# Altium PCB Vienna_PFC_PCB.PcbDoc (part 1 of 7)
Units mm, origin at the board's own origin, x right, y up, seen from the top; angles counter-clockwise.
Board outline 447.04 x 302.51 mm, 6 copper layers (Top Layer, Signal Layer 1, Signal Layer 2, Signal Layer 3, Signal Layer 4, Bottom Layer), stack 1.231 mm thick; 630 components, 255 nets, 1656 pads, 941 vias.
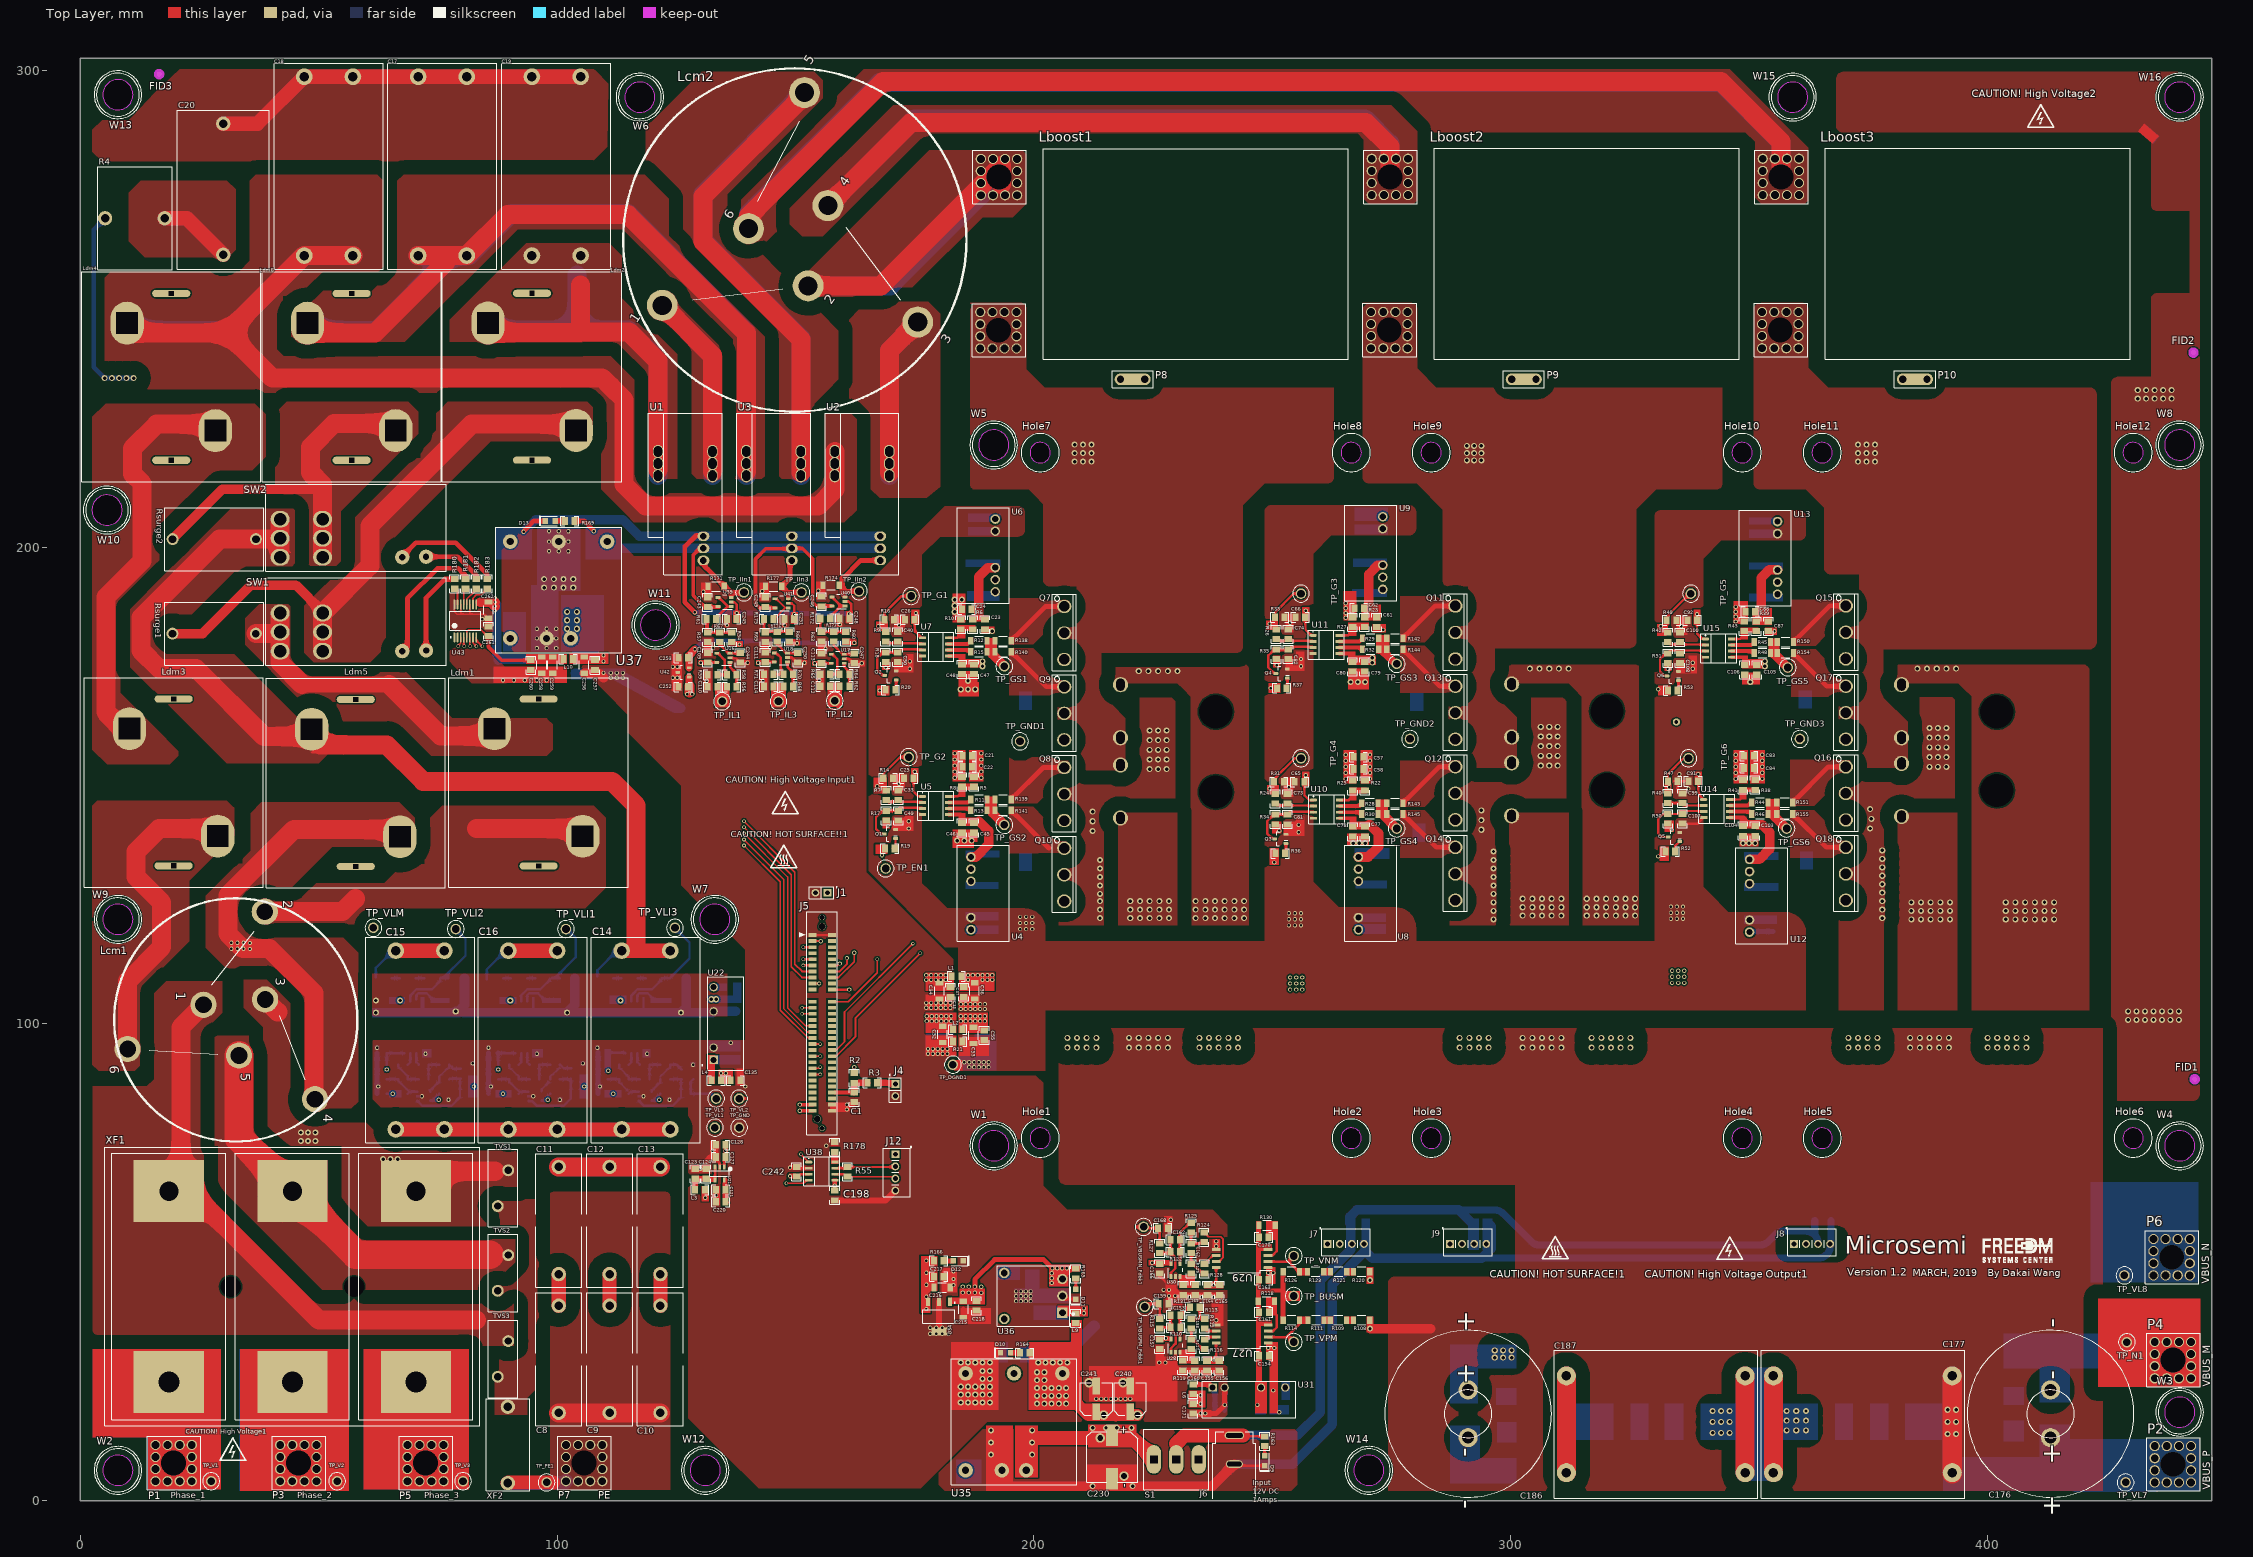
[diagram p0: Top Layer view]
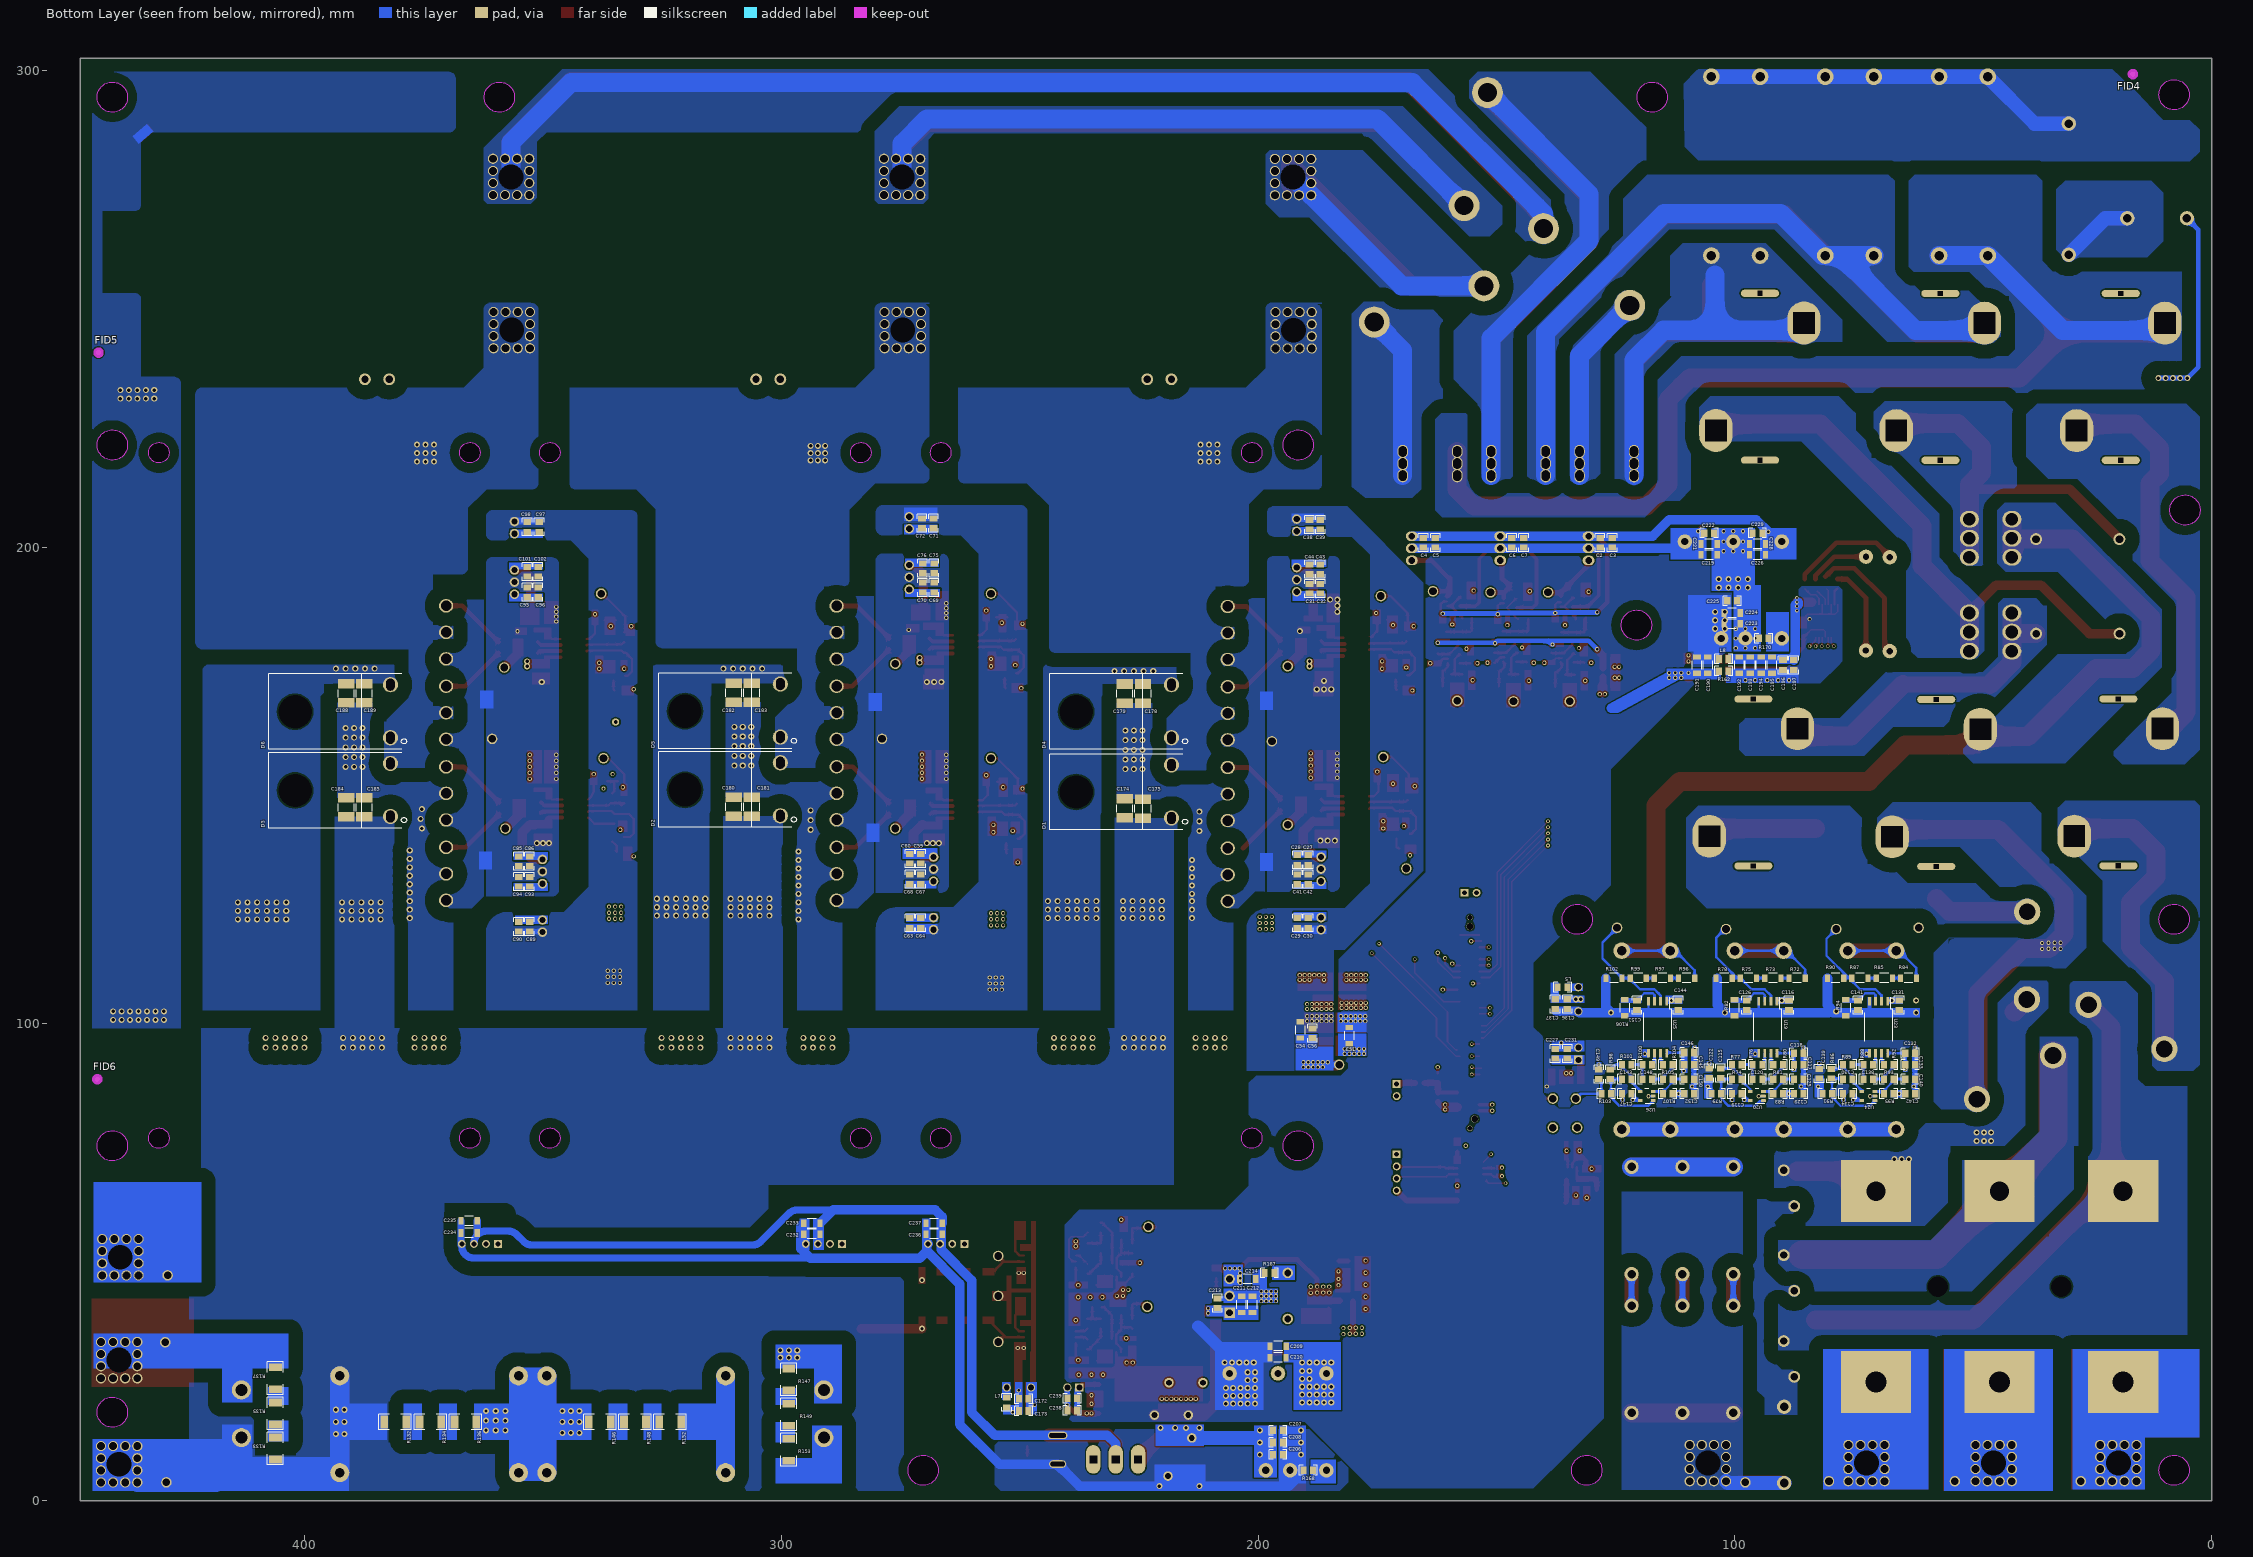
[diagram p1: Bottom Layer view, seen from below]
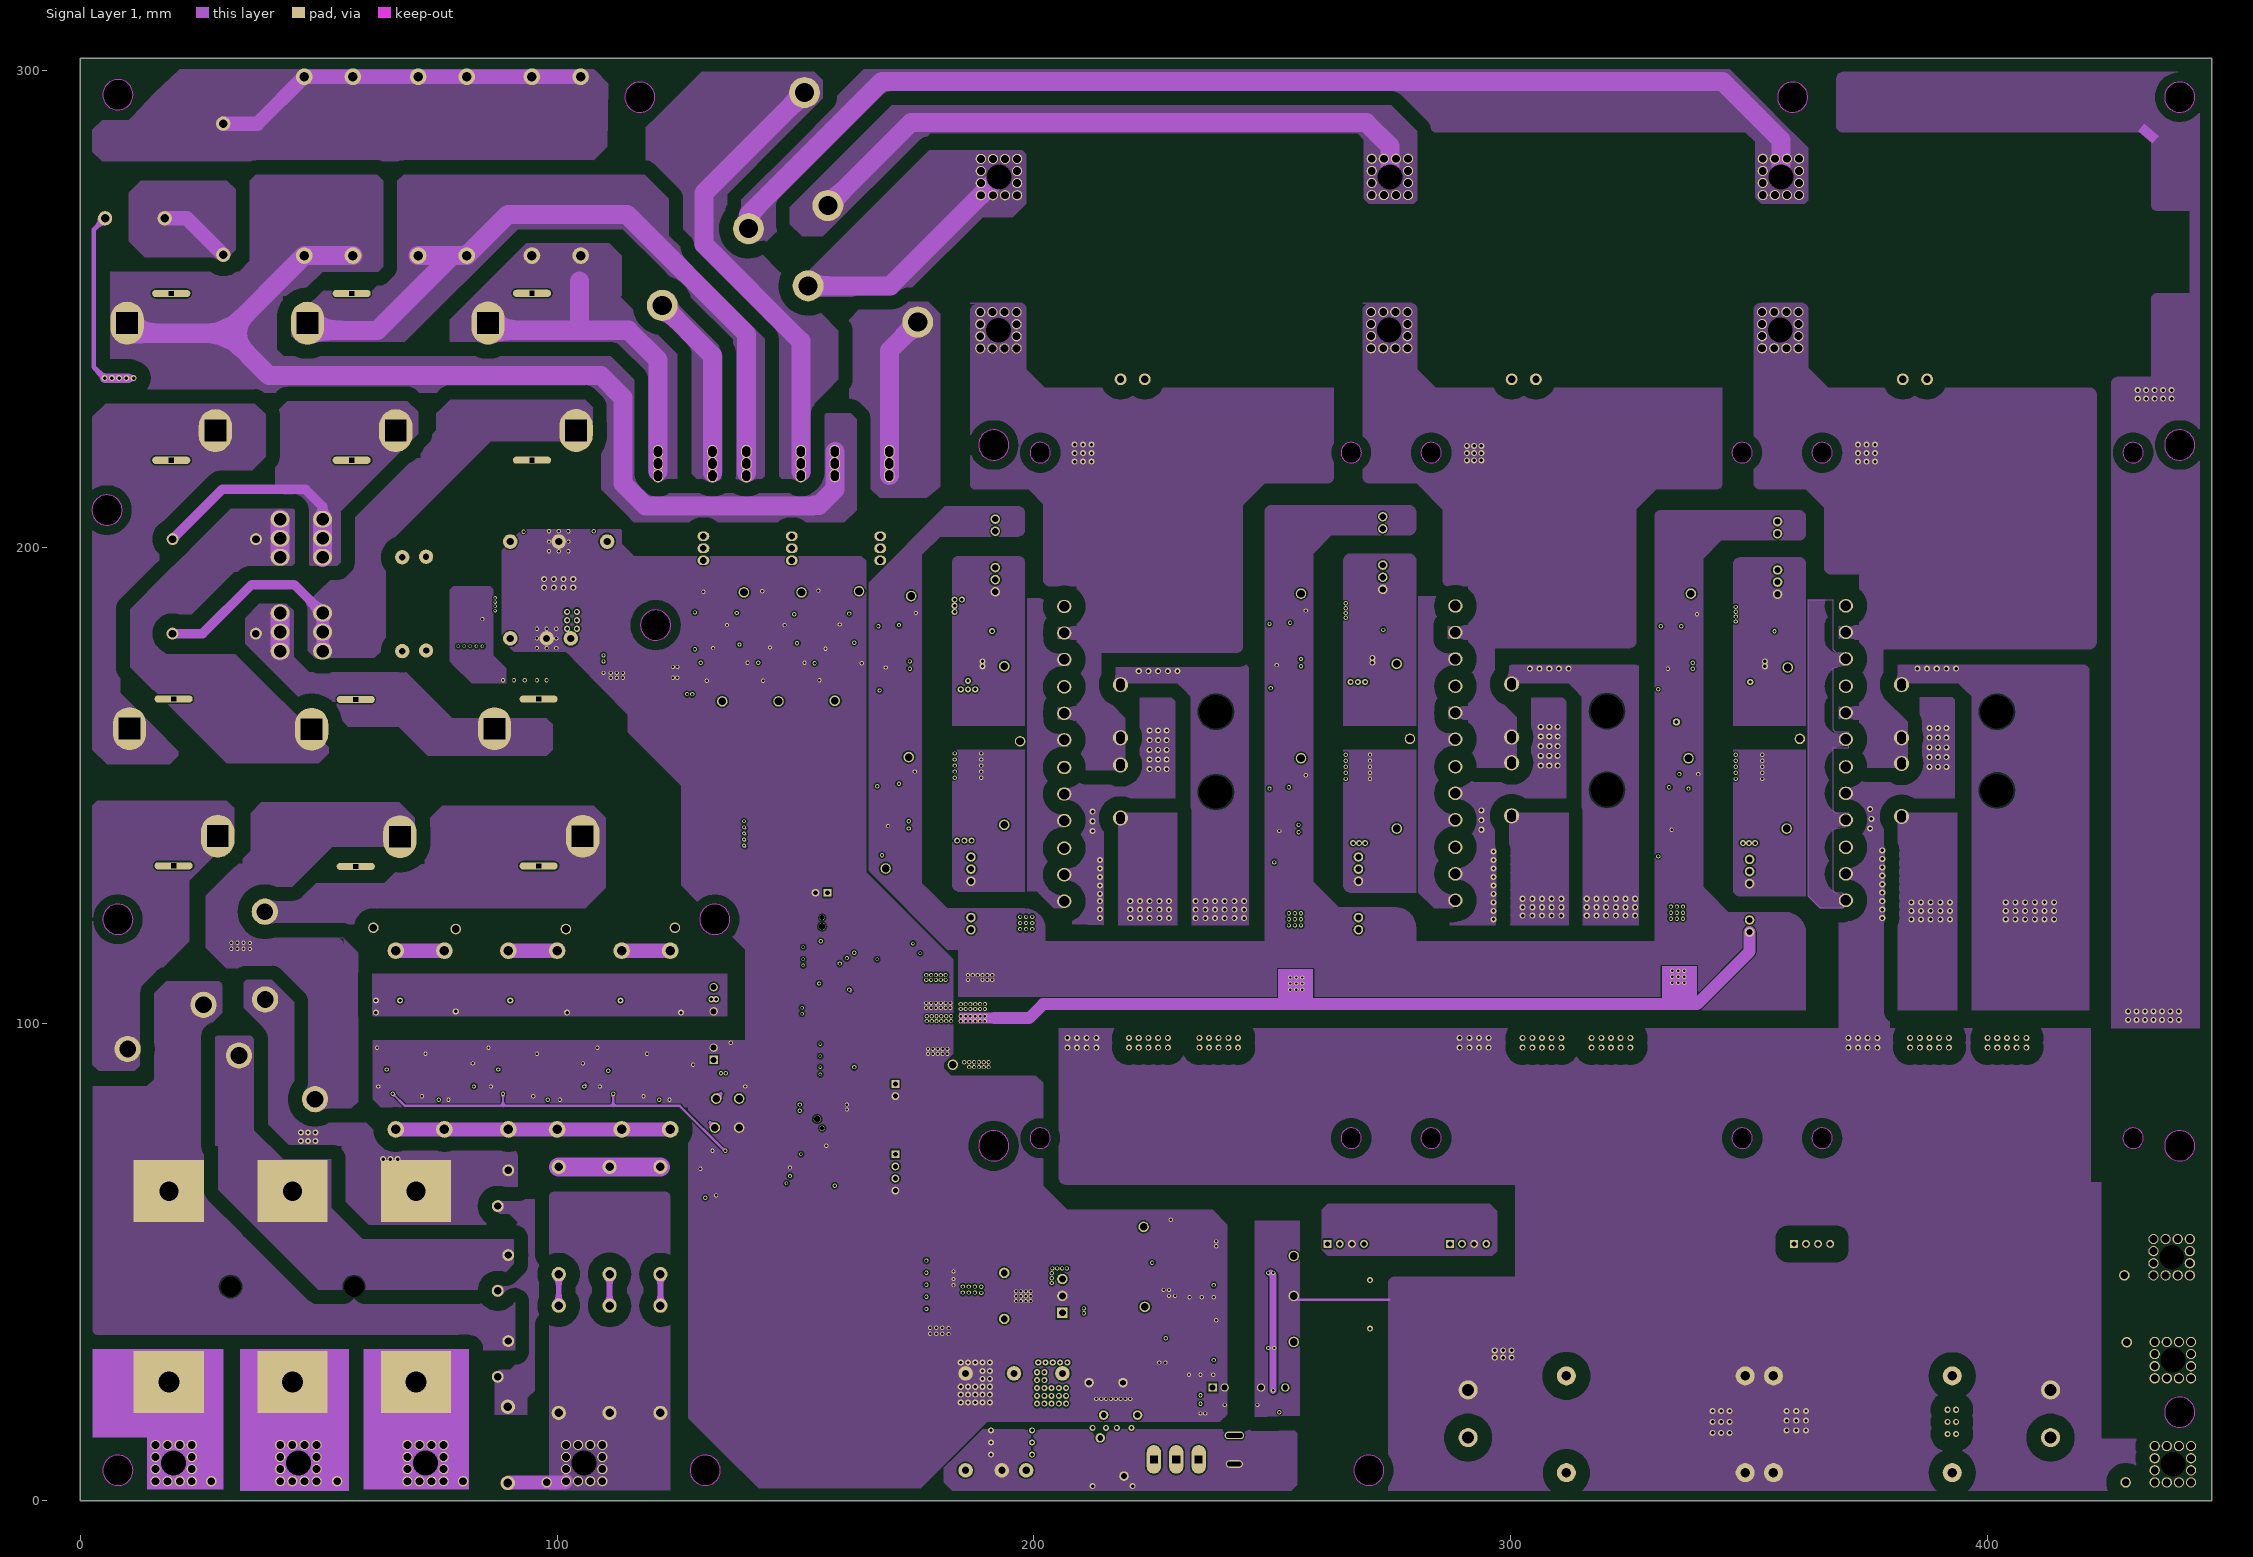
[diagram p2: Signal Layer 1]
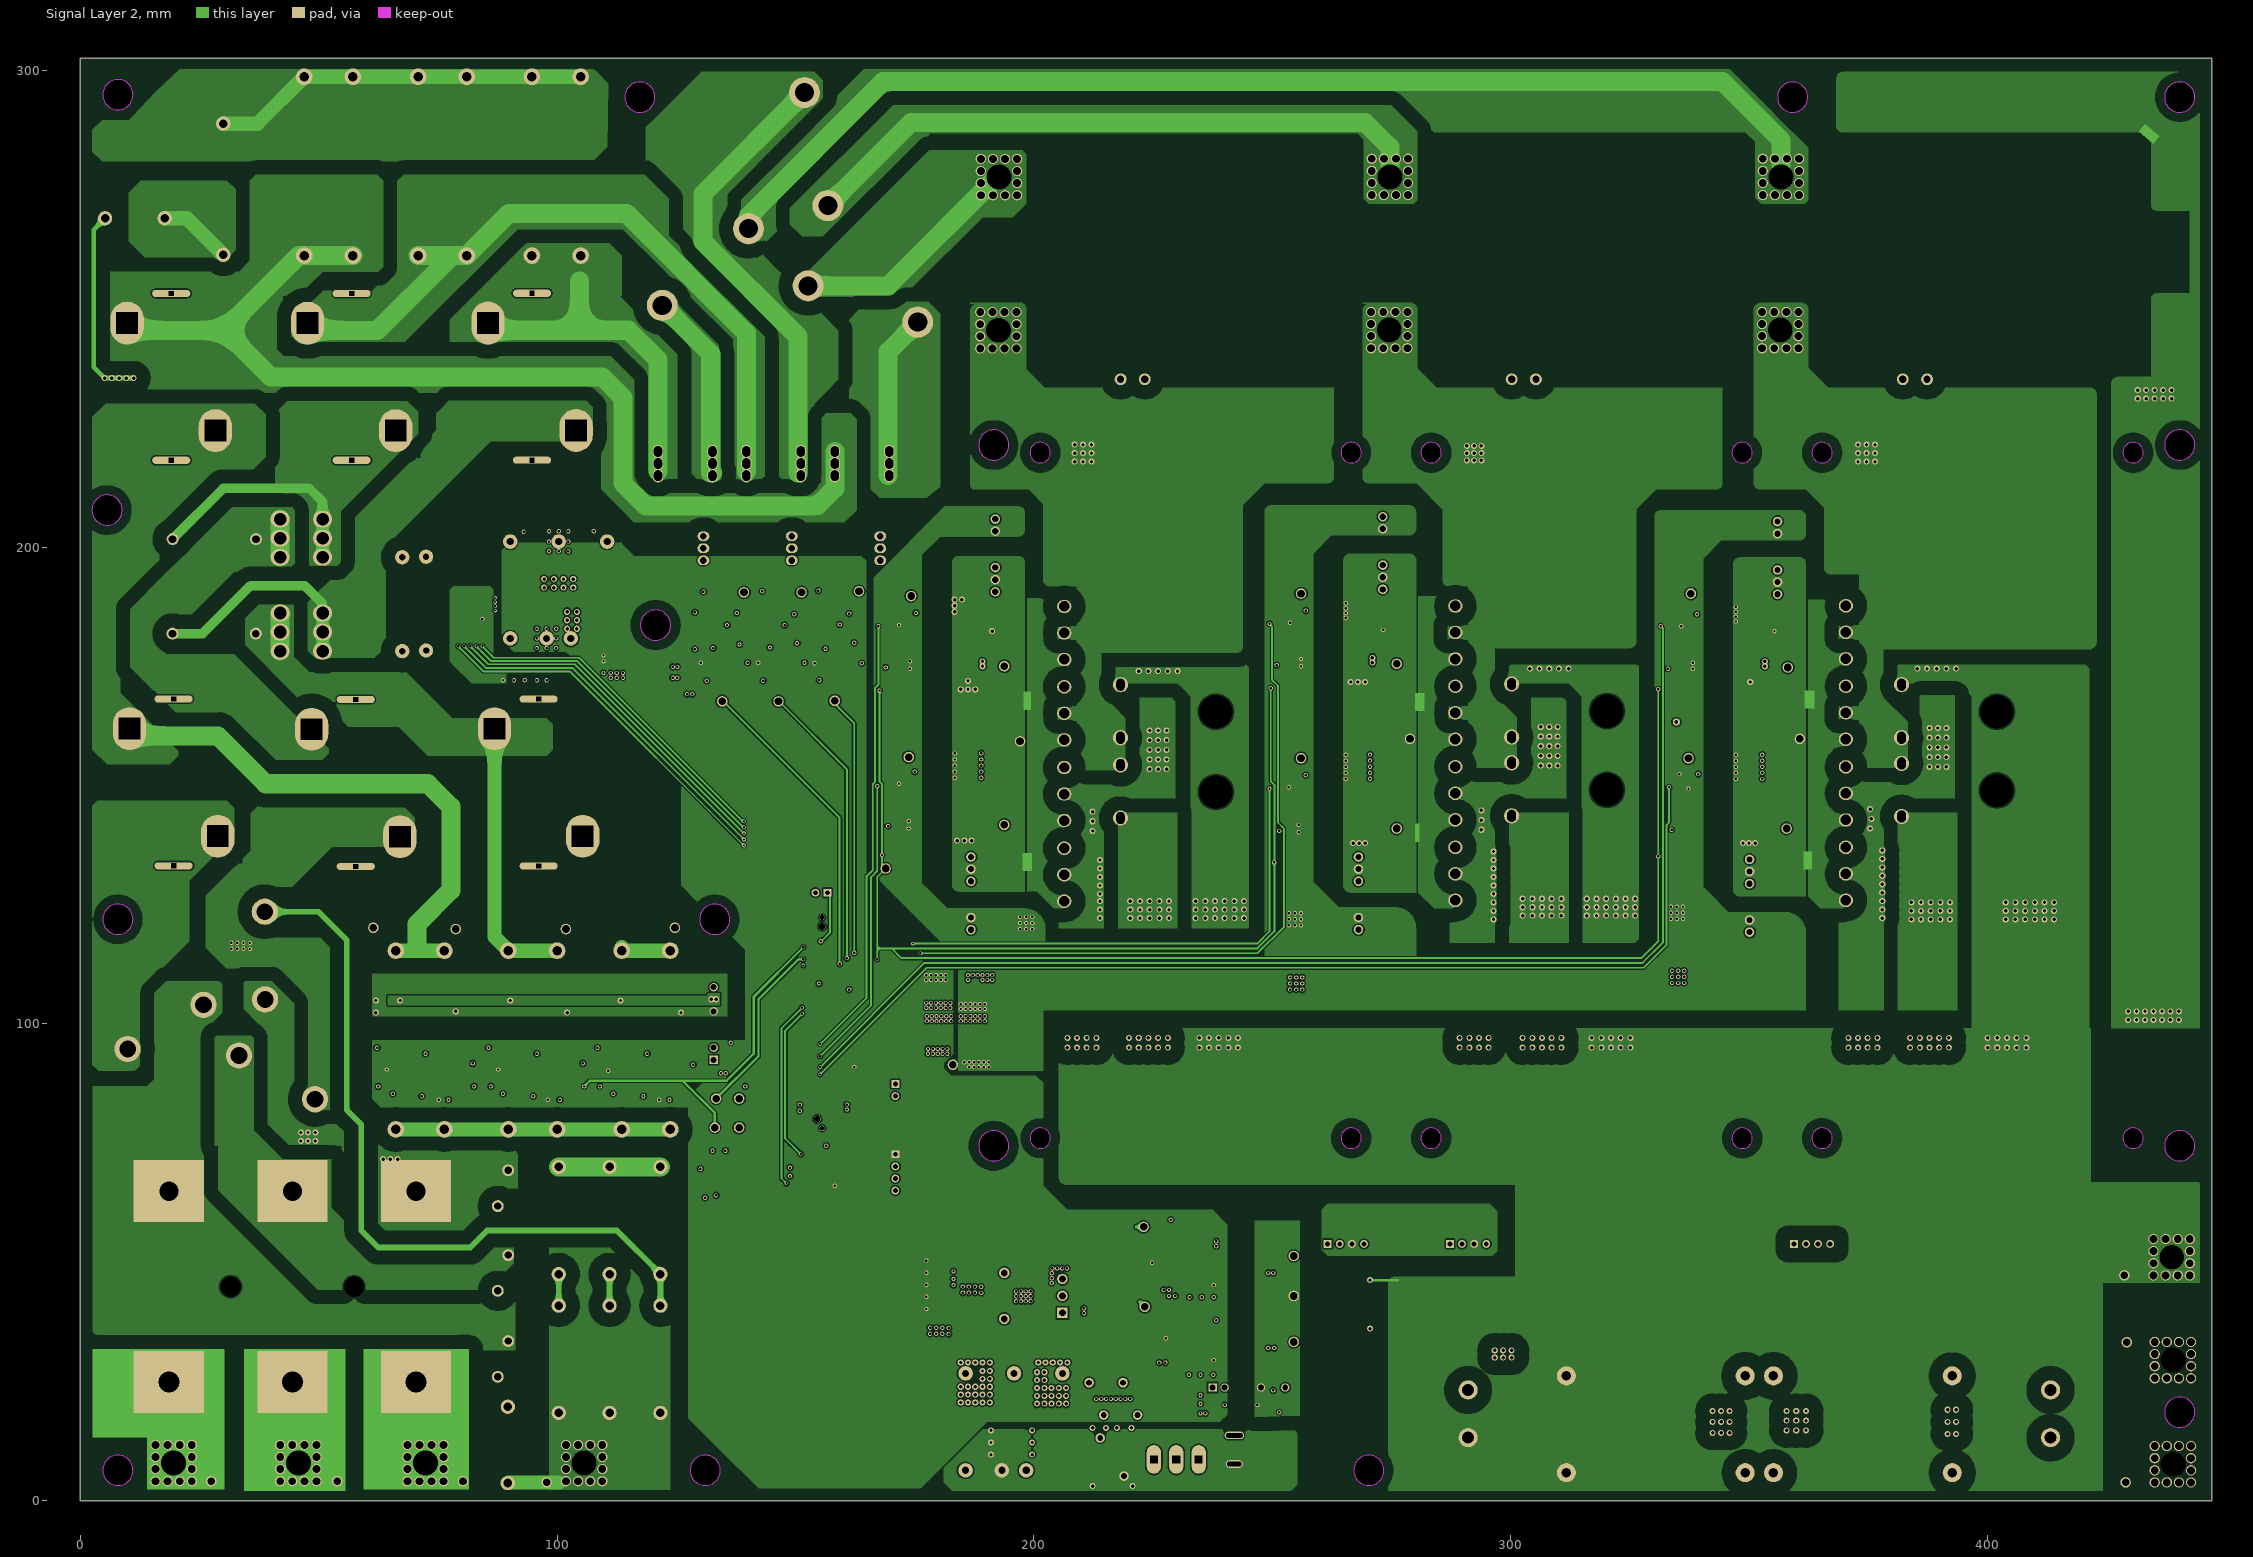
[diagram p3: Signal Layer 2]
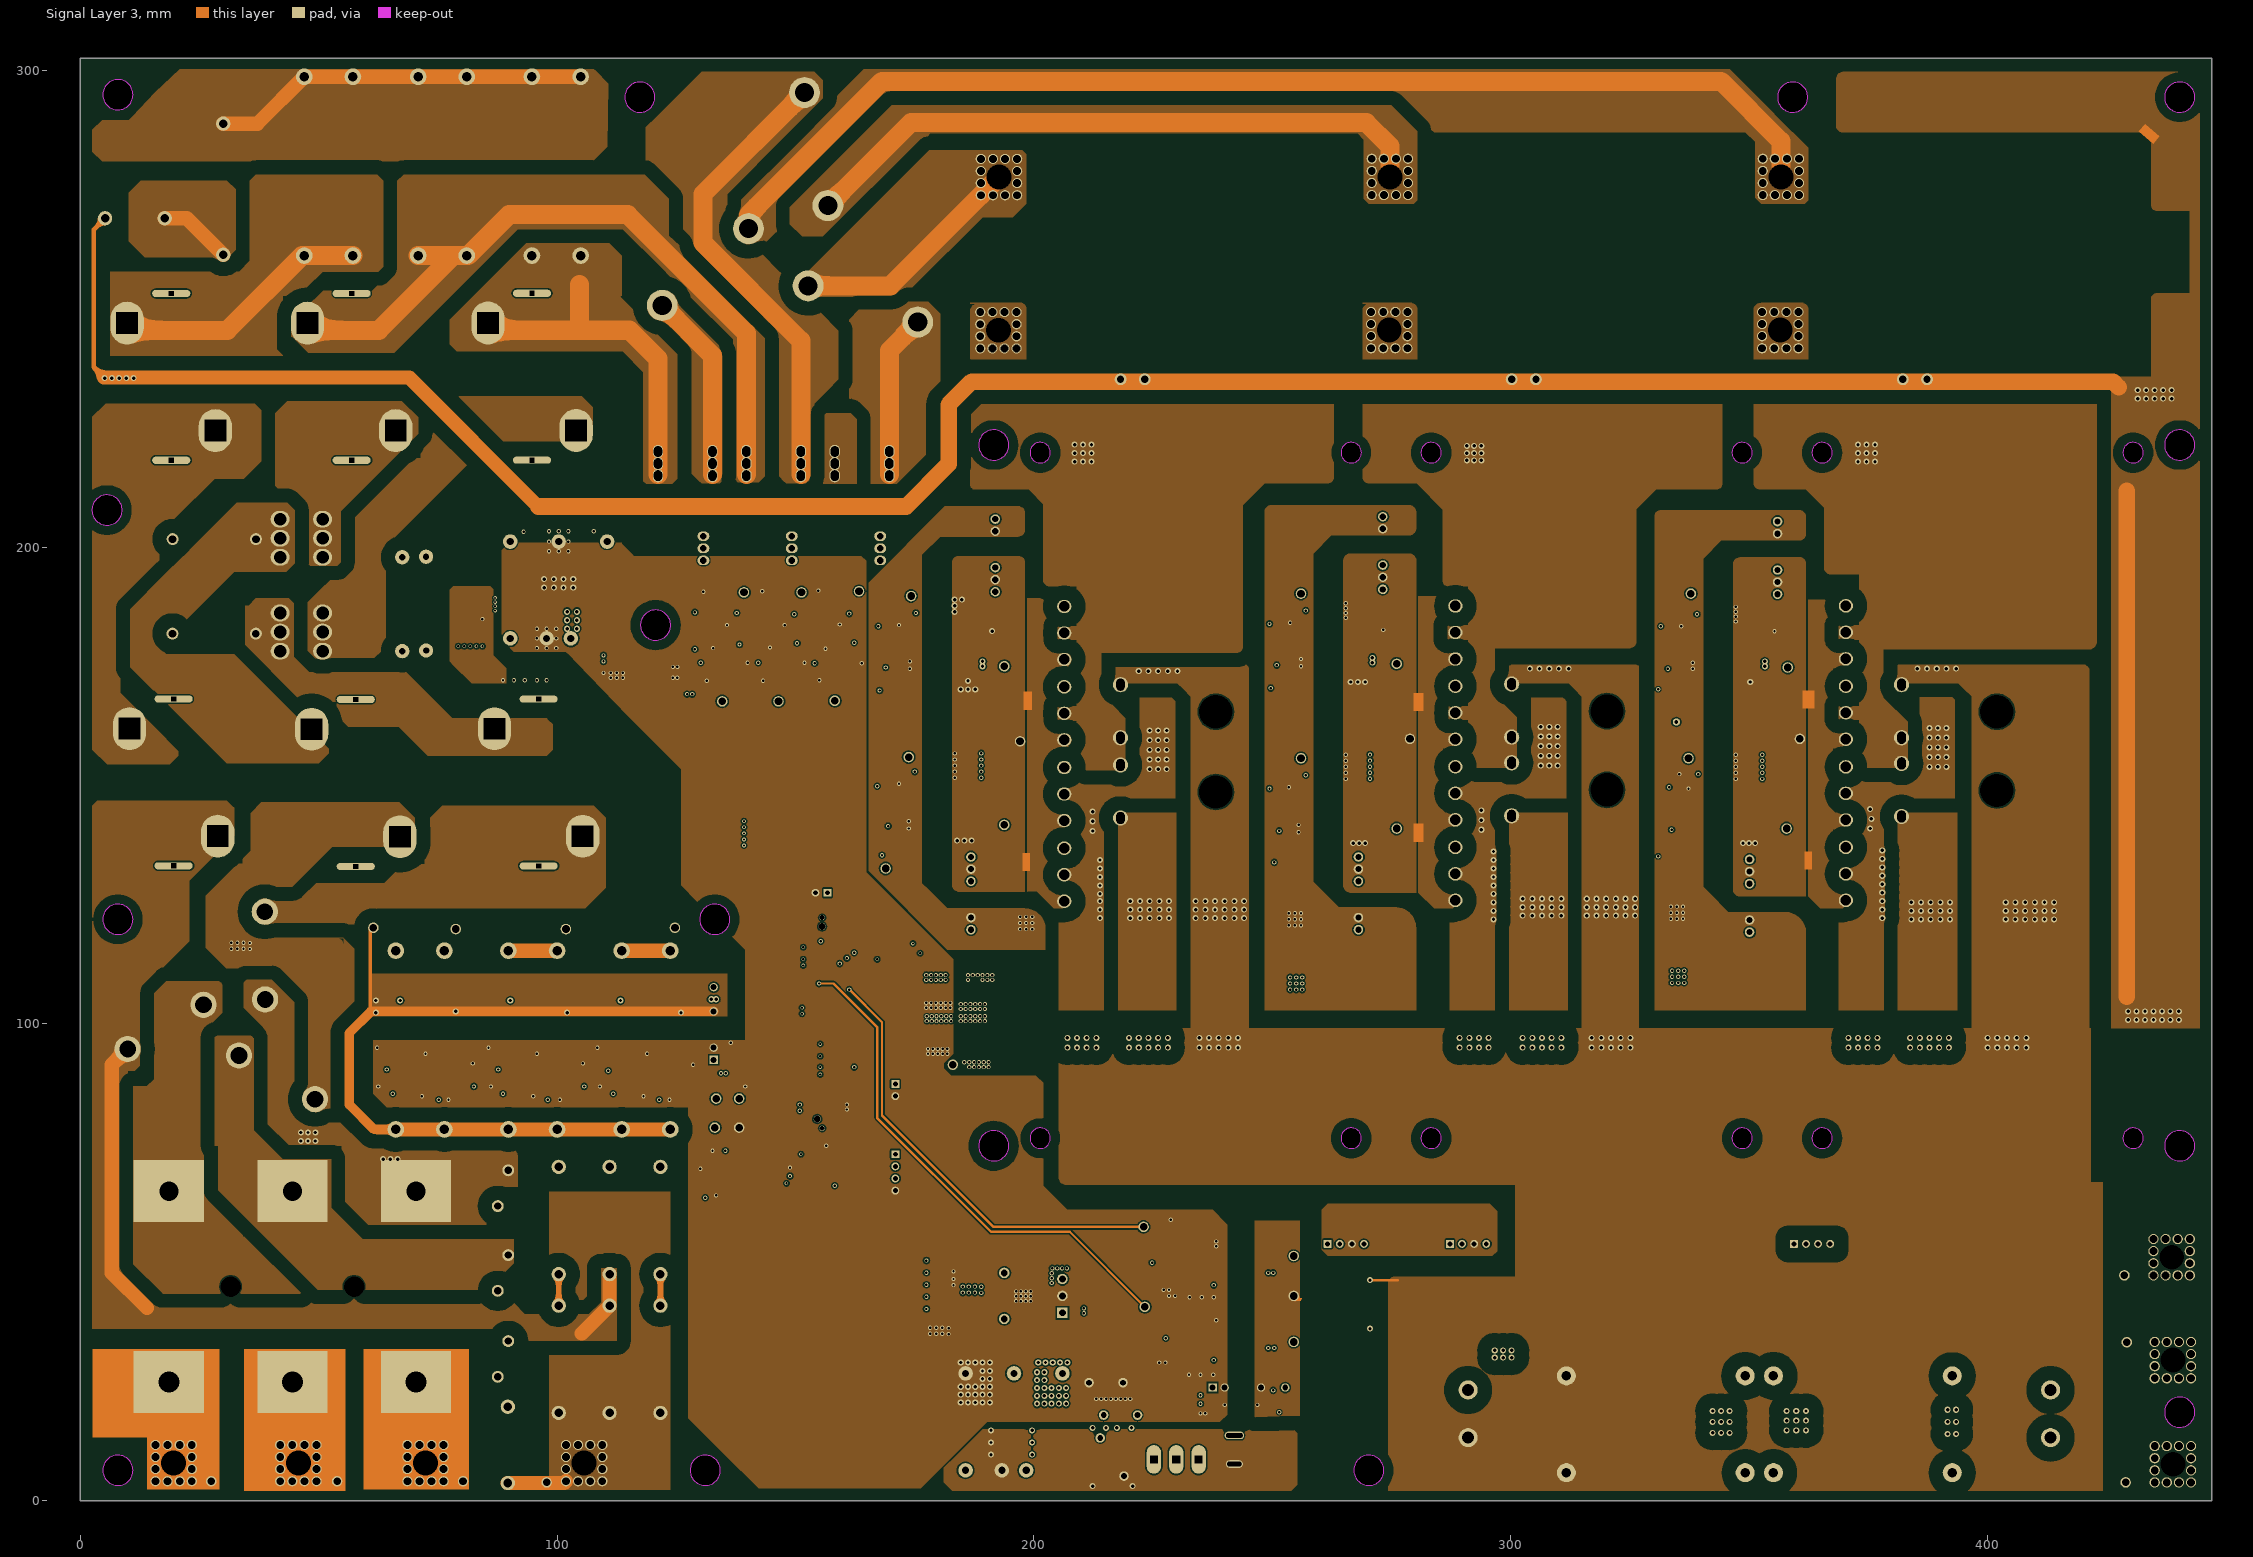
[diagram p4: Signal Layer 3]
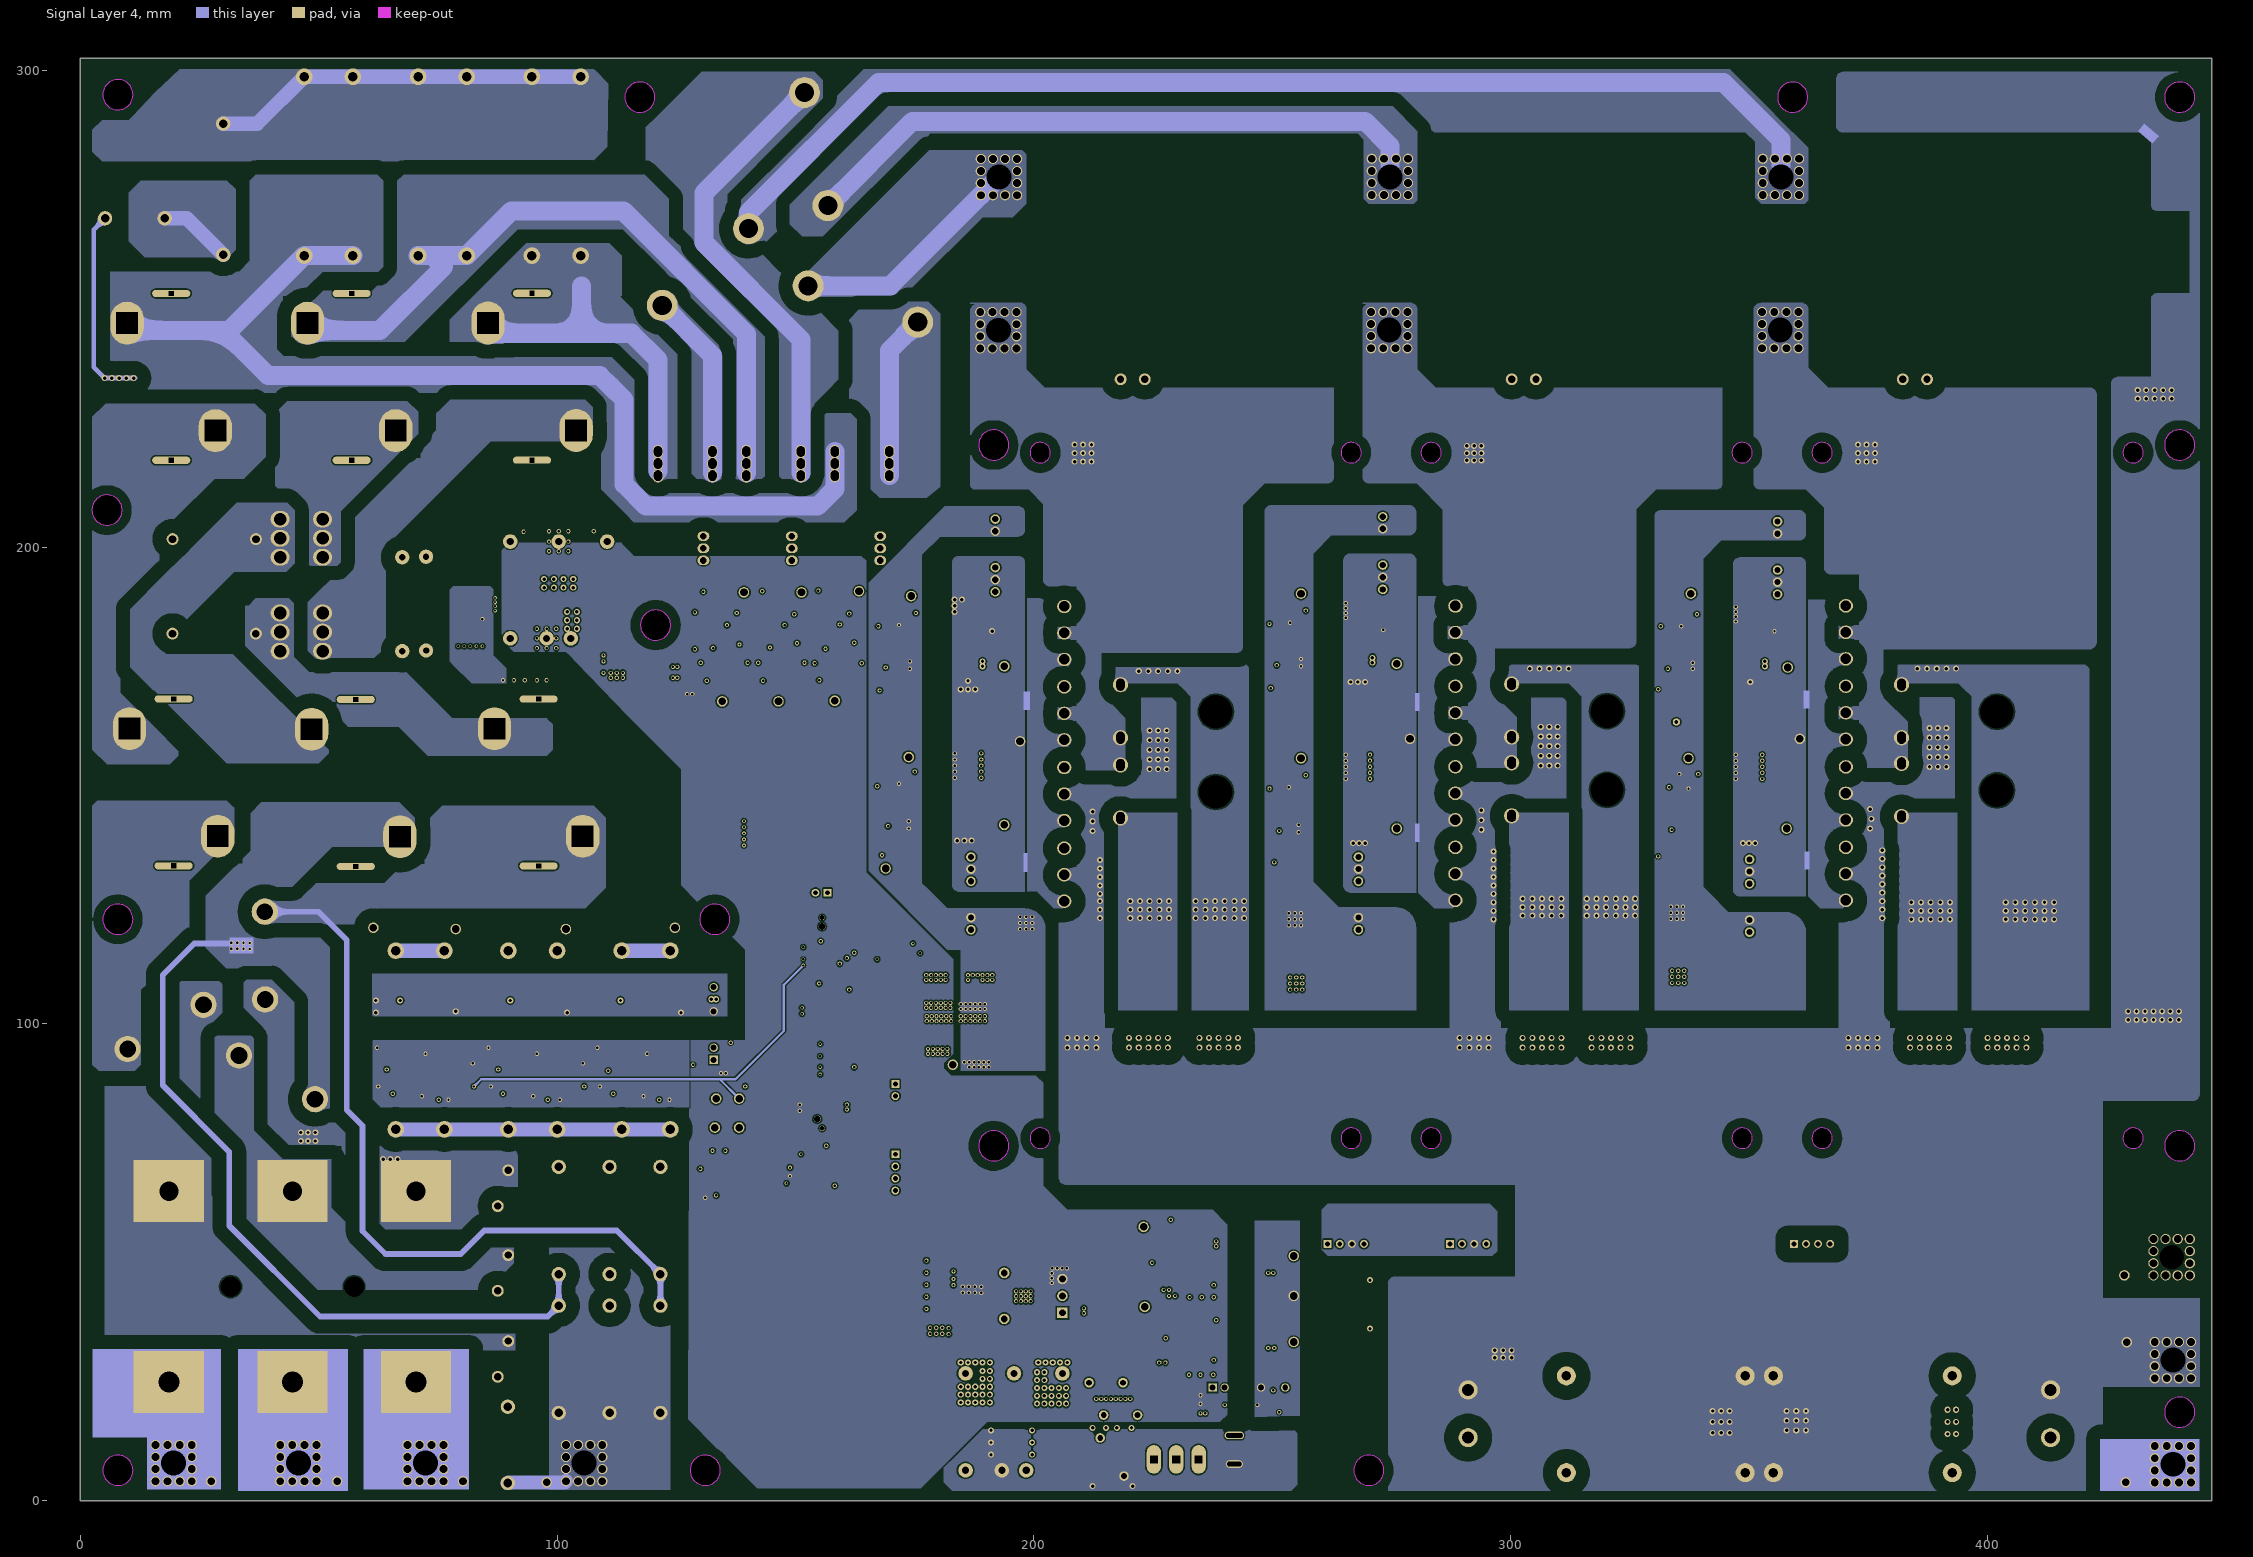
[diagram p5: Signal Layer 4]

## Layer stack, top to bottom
Top Solder: solder mask 0.0102, Solder Resist, Dk 3.5
Top Layer: signal copper 0.0356
Dielectric 1: core 0.254, FR-4, Dk 4.2
Signal Layer 1: signal copper 0.036
Dielectric 3: prepreg 0.127, Dk 4.2
Signal Layer 2: signal copper 0.036
Dielectric 4: core 0.254, Dk 4.2
Signal Layer 3: signal copper 0.036
Dielectric 5: prepreg 0.127, Dk 4.2
Signal Layer 4: signal copper 0.036
Dielectric 2: core 0.254, Dk 4.2
Bottom Layer: signal copper 0.0356
Bottom Solder: solder mask 0.0102, Solder Resist, Dk 3.5

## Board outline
0,0 0,302.514 447.04,302.514 447.04,0

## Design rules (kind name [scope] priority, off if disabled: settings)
Clearance "Keep out layer" [OnLayer('Keep-Out Layer')] p1: gap=0.305 ignorepadtopadclearanceinfootprint=TRUE except(0: Arc-Hole Track-Hole SMDPad-Hole THPad-Hole Via-Hole Fill-Hole Poly-Hole Region-Hole Text-Hole; 0.01: Arc-Text Track-Text SMDPad-Text THPad-Text Via-Text Fill-Text Poly-Text Region-Text Text-Text; 0.254: SMDPad-SMDPad; 1: Via-Poly; 2: Arc-Arc Arc-Track Arc-SMDPad Arc-THPad Arc-Via Arc-Fill Arc-Poly Arc-Region Track-Poly THPad-Poly)
Clearance Hardware [InNetClass('Hardware')] p2: gap=1.5 ignorepadtopadclearanceinfootprint=TRUE except(0: Arc-Hole Track-Hole SMDPad-Hole THPad-Hole Via-Hole Fill-Hole Poly-Hole Region-Hole Text-Hole)
Clearance "POWER Clearance" [InNetClass('POWER') vs InNetClass('POWER')] p3: gap=3 ignorepadtopadclearanceinfootprint=TRUE except(0: Arc-Hole Track-Hole SMDPad-Hole THPad-Hole Via-Hole Fill-Hole Poly-Hole Region-Hole Text-Hole; 0.254: Arc-Text Track-Text SMDPad-Text THPad-Text Via-Text Fill-Text Poly-Text Region-Text Text-Text; 1.95: SMDPad-SMDPad)
Clearance "POWER Relay Clearance" [InNetClass('POWER') vs InNetClass('Relay')] p4: gap=3 ignorepadtopadclearanceinfootprint=FALSE except(0: Arc-Hole Track-Hole SMDPad-Hole THPad-Hole Via-Hole Fill-Hole Poly-Hole Region-Hole Text-Hole; 0.254: Arc-Text Track-Text SMDPad-Text THPad-Text Via-Text Fill-Text Poly-Text Region-Text Text-Text)
Clearance "POWER Driver Signal Clearance" [InNetClass('POWER') vs InNetClass('Driver Signal')] p5: gap=3 ignorepadtopadclearanceinfootprint=TRUE except(0: Arc-Hole Track-Hole SMDPad-Hole THPad-Hole Via-Hole Fill-Hole Poly-Hole Region-Hole Text-Hole; 0.254: Arc-Text Track-Text SMDPad-Text THPad-Text Via-Text Fill-Text Poly-Text Region-Text Text-Text)
Clearance "POWER Current Clearance" [InNetClass('POWER') vs InNetClass('InductorCurrent')] p6: gap=3 ignorepadtopadclearanceinfootprint=FALSE except(0: Arc-Hole Track-Hole SMDPad-Hole THPad-Hole Via-Hole Fill-Hole Poly-Hole Region-Hole Text-Hole; 0.254: Arc-Text Track-Text SMDPad-Text THPad-Text Via-Text Fill-Text Poly-Text Region-Text Text-Text)
Clearance "POWER Power Supply Clearance" [InNetClass('POWER') vs InNetClass('PowerSupply')] p7: gap=3 ignorepadtopadclearanceinfootprint=FALSE except(0: Arc-Hole Track-Hole SMDPad-Hole THPad-Hole Via-Hole Fill-Hole Poly-Hole Region-Hole Text-Hole; 0.254: Arc-Text Track-Text SMDPad-Text THPad-Text Via-Text Fill-Text Poly-Text Region-Text Text-Text)
Clearance "POWER Hardware Clearance" [InNetClass('POWER') vs InNetClass('Hardware')] p8: gap=3 ignorepadtopadclearanceinfootprint=FALSE except(0: Arc-Hole Track-Hole SMDPad-Hole THPad-Hole Via-Hole Fill-Hole Poly-Hole Region-Hole Text-Hole; 0.254: Arc-Text Track-Text SMDPad-Text THPad-Text Via-Text Fill-Text Poly-Text Region-Text Text-Text)
Clearance "POWER Controller Clearance" [InNetClass('POWER') vs InNetClass('Controller')] p9: gap=3 ignorepadtopadclearanceinfootprint=FALSE except(0: Arc-Hole Track-Hole SMDPad-Hole THPad-Hole Via-Hole Fill-Hole Poly-Hole Region-Hole Text-Hole; 0.254: Arc-Text Track-Text SMDPad-Text THPad-Text Via-Text Fill-Text Poly-Text Region-Text Text-Text)
Clearance [All] p10: gap=0.305 ignorepadtopadclearanceinfootprint=TRUE
Height [All] p1: minheight=0 maxheight=76.2 prefheight=12.7
HoleSize [All] p1: absolutevalues=TRUE maxlimit=8 minlimit=0.025 maxpercent=80.000 minpercent=20.000
MinimumSolderMaskSliver [All] p1: minsoldermaskwidth=0
PolygonConnect [All] p1: connectstyle=Direct reliefconductorwidth=0.254 reliefentries=4 polygonreliefangle="90 Angle" airgapwidth=0.254
RoutingVias [All] p1: holewidth=0.711 width=0.889 viastyle="Through Hole" minholewidth=0.381 minwidth=0.508 maxholewidth=0.508 maxwidth=1.27
SilkToSilkClearance [All] p1: silktosilkclearance=0
SilkToSolderMaskClearance [IsPad] p1: minsilkscreentomaskgap=0 clearancetoexposedcopper=TRUE
SolderMaskExpansion [All] p1: expansion=0.102
Width "POWER Width" [InNetClass('POWER')] p1: maxlimit=9 minlimit=0.508 preferedwidth=4 toplayer_minwidth=2 midlayer4_minwidth=1 minimp=50.000000 maximp=50.000000 favimp=50.000000
Width [All] p2: maxlimit=5.08 minlimit=0.254 preferedwidth=0.508 midlayer1_maxwidth=2.54 midlayer2_maxwidth=2.54 midlayer3_maxwidth=2.54 midlayer4_maxwidth=2.54 minimp=50.000000 maximp=50.000000 favimp=50.000000
25 further rules are at their usual default settings.

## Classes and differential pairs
component class Vienna_PFC_Overall: P1 P2 P3 P4 P5 P6 P7
component class U_Vienna_PFC_Relay: C190 C191 C192 C193 C194 C195 C196 C197 C256 C257 C258 C259 C260 C261 C262 L8 L10 R162 R180 R181 R182 R183 U43
component class U_Vienna_PFC_PowerSupply: C206 C207 C208 C209 C210 C211 C212 C213 C214 C215 C216 C217 C218 C219 C221 C222 C223 C224 C225 C226 C228 C229 C230 C232 C233 C234 C235 C236 C237 C240 C241 D9 D10 D11 D12 D13 J6 J7 J8 J9 L9 R163 R164 R165 R166 R167 R168 R169 R170 S1 U34 U35 U36 U37
component class U_Vienna_PFC_PowerStage: C174 C175 C176 C177 C178 C179 C180 C181 C182 C183 C184 C185 C186 C187 C188 C189 D1 D2 D3 D4 D5 D6 Lboost1 Lboost2 Lboost3 Q7 Q8 Q9 Q10 Q11 Q12 Q13 Q14 Q15 Q16 Q17 Q18 R132 R133 R134 R135 R136 R137 R138 R139 R140 R141 R142 R143 R144 R145 R146 R147 R148 R149 R150 R151 R152 R153 R154 R155 TP_N1 TP_VL7 TP_VL8
component class U_Vienna_PFC_OutputVoltageSensor: C153 C154 C155 C156 C157 C158 C159 C160 C161 C162 C163 C164 C165 C166 C167 C168 C169 C170 C171 C172 C173 C238 C239 L6 L7 R108 R109 R110 R111 R112 R113 R114 R115 R116 R117 R118 R119 R120 R121 R122 R123 R124 R125 R126 R127 R128 R129 R130 R131 TP_BUSM TP_VBUSMN_Fdbk1 TP_VBUSPM_Fdbk1 TP_VNM TP_VPM U27 U28 U29 U30 U31
component class U_Vienna_PFC_InputVoltageSensor: C115 C116 C117 C118 C119 C120 C121 C122 C123 C124 C125 C126 C127 C128 C129 C130 C131 C132 C133 C134 C135 C136 C137 C138 C139 C140 C141 C142 C143 C144 C145 C146 C147 C148 C149 C150 C151 C152 C220 C227 C231 L3 L4 L5 R72 R73 R74 R75 R76 R77 R78 R79 R80 R81 R82 R83 R84 R85 R86 R87 R88 R89 R90 R91 R92 R93 R94 R95 R96 R97 R98 R99 R100 R101 R102 R103 R104 R105 R106 R107 TP_GND TP_VL1 TP_VL2 TP_VL3 TP_VLI1 TP_VLI2 TP_VLI3 TP_VLM U19 U20 U21 U22 U23 U24 U25 U26
component class U_Vienna_PFC_InductorCurrentSensor: C109 C110 C111 C112 C113 C114 C243 C244 C245 C246 C247 C248 C249 C250 C251 C252 C253 R54 R56 R57 R58 R59 R60 R61 R62 R63 R64 R65 R66 R67 R68 R69 R70 R71 R171 R172 R173 R174 R175 R176 R177 TP_IIn1 TP_IIn2 TP_IIn3 TP_IL1 TP_IL2 TP_IL3 U16 U17 U18 U39 U40 U41 U42
component class U_Vienna_PFC_GateDriver: C21 C22 C23 C24 C25 C26 C27 C28 C29 C30 C31 C32 C33 C34 C35 C36 C37 C38 C39 C40 C41 C42 C43 C44 C45 C46 C47 C48 C49 C50 C51 C52 C53 C54 C55 C56 C57 C58 C59 C60 C61 C62 C63 C64 C65 C66 C67 C68 C69 C70 C71 C72 C73 C74 C75 C76 C77 C78 C79 C80 C81 C82 C83 C84 C85 C86 C87 C88 C89 C90 C91 C92 C93 C94 C95 C96 C97 C98 C99 C100 C101 C102 C103 C104 C105 C106 C107 C108 L1 L2 Q1 Q2 Q3 Q4 Q5 Q6 R5 R6 R7 R8 R9 R10 R11 R12 R13 R14 R15 R16 R17 R18 R19 R20 R21 R22 R23 R24 R25 R26 R27 R28 R29 R30 R31 R32 R33 R34 R35 R36 R37 R38 R39 R40 R41 R42 R43 R44 R45 R46 R47 R48 R49 R50 R51 R52 R53 TP_DGND1 TP_EN1 TP_G1 TP_G2 TP_G3 TP_G4 TP_G5 TP_G6 TP_GND1 TP_GND2 TP_GND3 TP_GS1 TP_GS2 TP_GS3 TP_GS4 TP_GS5 TP_GS6 U4 U5 U6 U7 U8 U9 U10 U11 U12 U13 U14 U15
component class U_Vienna_PFC_EMIFilter: C2 C3 C4 C5 C6 C7 C8 C9 C10 C11 C12 C13 C14 C15 C16 C17 C18 C19 C20 Lcm1 Lcm2 Ldm1 Ldm2 Ldm3 Ldm4 Ldm5 Ldm6 p8 p9 p10 R4 Rsurge1 Rsurge2 SW1 SW2 TP_PE1 TP_V1 TP_V2 TP_V3 TVS1 TVS2 TVS3 U1 U2 U3 XF1 XF2
component class U_Vienna_PFC_Controller: C1 C198 C242 J1 J4 J5 J12 R2 R3 R55 R178 U38
component class U_EVM_Hardware: "CAUTION! High Voltage1" "CAUTION! High Voltage2" "CAUTION! High Voltage Input1" "CAUTION! High Voltage Output1" "CAUTION! High Voltage!" "CAUTION! HOT SURFACE!1" "CAUTION! HOT SURFACE!!1" "CAUTION! Read User Guide Before Operating1" FAN1 FAN2 FAN3 FID1 FID2 FID3 FID4 FID5 FID6 H1 H2 H3 H4 H5 H6 H7 H8 H9 H10 H11 H12 H13 H14 H15 H16 H17 H18 H19 H20 H21 H22 H23 H24 H25 H26 H27 H28 H29 H30 H31 H32 H33 H34 H35 H36 H37 H38 H39 H40 H41 H42 H43 H44 H45 H46 H47 H48 Hole1 Hole2 Hole3 Hole4 Hole5 Hole6 Hole7 Hole8 Hole9 Hole10 Hole11 Hole12 Logo1 Logo2 Logo3 Power1 SH-J1 SH-J2 SIL1 SIL2 SIL3 SIL4 SIL5 SIL6 SIL7 SIL8 SIL9 SIL10 SIL11 SIL12 TIDM-1 W1 W2 W3 W4 W5 W6 W7 W8 W9 W10 W11 W12 W13 W14 W15 W16 XF3 XF4 XF5 ZZ1 ZZ2 ZZ3 ZZ4 ZZ5
net class InputVoltage: 5V_N +3.3V +5V GND NetC14_2 NetC15_2 NetC16_2 NetC115_1 NetC115_2 NetC120_1 NetC120_2 NetC122_2 NetC123_1 NetC125_1 NetC126_1 NetC130_1 NetC130_2 NetC138_1 NetC138_2 NetC139_2 NetC140_1 NetC141_1 NetC143_1 NetC143_2 NetC148_1 NetC148_2 NetC149_2 NetC150_1 NetC151_1 NetC227_1 NetL5_1 NetR72_1 NetR73_1 NetR75_1 NetR76_1 NetR80_1 NetR84_1 NetR85_1 NetR87_1 NetR88_1 NetR92_1 NetR96_1 NetR97_1 NetR99_1 NetR100_1 NetR104_1 REF_1V65 REF_3V3 V_N_MEAS
net class GateDriver: +3.3V +3.3V_D +12V +12V_D +20V1 +20V2 +20V3 +20V4 +20V5 +20V6 -5V1 -5V2 -5V3 -5V4 -5V5 -5V6 DGND EN_PWM GND GND1 GND3 GND5 NetC33_1 NetC40_1 NetC49_1 NetC50_1 NetC73_1 NetC74_1 NetC81_1 NetC82_1 NetC99_1 NetC100_1 NetC107_1 NetC108_1 NetJ5_37 NetJ5_40 NetJ5_41 NetJ5_42 NetJ5_45 NetJ5_47 NetQ1_1 NetQ2_1 NetQ3_1 NetQ4_1 NetQ5_1 NetQ6_1 NetR5_1 NetR6_1 NetR11_1 NetR11_2 NetR12_1 NetR12_2 NetR13_1 NetR15_1 NetR22_1 NetR23_1 NetR28_1 NetR28_2 NetR29_1 NetR29_2 NetR30_1 NetR32_1 NetR38_1 NetR39_1 NetR44_1 NetR44_2 NetR45_1 NetR45_2 NetR46_1 NetR48_1
net class Hardware: NetFAN1_1 NetFAN1_2 NetFAN2_1 NetFAN2_2 NetFAN3_1 NetFAN3_2 NetH1_1 NetH2_1 NetH3_1 NetH4_1 NetH5_1 NetH6_1 NetH7_1 NetH8_1 NetH9_1 NetH10_1 NetH11_1 NetScrew_test1_0 NetScrew_test2_0 NetScrew_test3_0 NetScrew_test4_0 NetScrew_test5_0 NetScrew_test6_0 NetScrew_test7_0 NetScrew_test8_0 NetScrew_test9_0 NetScrew_test10_0 NetScrew_test11_0 NetScrew_test12_0 NetScrew_test13_0 NetScrew_test14_0 NetScrew_test_0
net class PowerSupply: 12V_IN +3.3V +5V +12V +15V -15V GND GND_IN NetC206_1 NetC211_1 NetD9_2 NetD10_2 NetD11_2 NetD12_2 NetD13_2 NetJ7_3 NetJ7_4 NetJ8_3 NetJ8_4 NetJ9_3 NetJ9_4 NetR167_2 NetR168_1 NetR170_1 NetU35_5 NetU36_5
net class Relay: +3.3V +3.3V_2 +12V +12V_D2 DGND2 GND NetJ5_13 NetJ5_15 NetJ5_31 NetJ5_33 NetJ5_35 NetR180_1 NetR180_2 NetR181_1 NetR181_2 NetR182_1 NetR182_2 NetR183_1 NetR183_2
net class Controller: +3.3V +5V Button CAN_H CAN_L CAN_RX CAN_TX DACOUT EN_PWM GND NetC110_1 NetC112_1 NetC114_1 NetC122_2 NetC139_2 NetC149_2 NetC159_2 NetC168_2 NetJ4_1 NetJ5_1 NetJ5_2 NetJ5_3 NetJ5_4 NetJ5_5 NetJ5_6 NetJ5_8 NetJ5_12 NetJ5_13 NetJ5_14 NetJ5_15 NetJ5_17 NetJ5_23 NetJ5_30 NetJ5_31 NetJ5_32 NetJ5_33 NetJ5_35 NetJ5_36 NetJ5_37 NetJ5_39 NetJ5_40 NetJ5_41 NetJ5_42 NetJ5_43 NetJ5_44 NetJ5_45 NetJ5_47 NetJ5_56 NetJ5_57 NetJ5_66 NetJ5_68 NetJ5_69 NetJ5_70 NetJ5_71 NetJ5_72 NetJ5_73 NetJ5_74 NetJ5_75 NetJ5_76 NetJ5_77 NetJ5_78 NetJ5_79 NetJ5_80 NetJ5_81 NetJ5_82 NetJ5_85 NetJ5_86 NetJ5_87 NetJ5_88 NetJ5_89 NetJ5_90 NetJ5_91 NetJ5_92 NetJ5_93 NetJ5_94 NetJ5_95 NetJ5_96 NetJ5_99 NetJ5_100 NetJ5_101 NetJ5_102 NetJ5_103 NetJ5_104 NetJ5_105 NetJ5_106 NetJ5_107 NetJ5_108 NetJ5_109 NetJ5_110 NetJ5_113 NetJ5_114 NetJ5_115 NetJ5_116 NetJ5_117 NetJ5_118 NetJ5_119 NetJ5_120 NetJ5_121 NetJ5_122 NetJ5_123 NetJ5_124 NetJ5_125 NetJ5_126 NetJ5_127 NetJ5_128 NetJ5_129 NetJ5_130 NetJ5_131 NetJ5_132 NetJ5_133 NetJ5_134 NetJ5_136 NetJ5_137 NetJ5_138 NetJ5_159 NetJ5_160 NetJ5_161 NetJ5_162 NetJ5_163 NetJ5_164 NetJ5_165 NetJ5_166 NetJ5_167 NetJ5_168 NetJ5_169 NetJ5_170 NetJ5_171 NetJ5_172 NetJ5_173 NetJ5_174 NetJ5_175 NetJ5_176 NetJ5_177 NetJ5_178 NetR178_1
net class InductorCurrent: +3.3V +5V +15V -15V GND NetC110_1 NetC112_1 NetC114_1 NetC244_1 NetC247_1 NetC250_1 NetR54_1 NetR56_1 NetR58_1 NetR60_1 NetR61_1 NetR62_1 NetR64_1 NetR66_1 NetR68_1 NetR70_1 NetR171_2 NetR172_1 NetR174_2 NetR175_1 NetR177_2 REF_3V3_2
net class OutputVoltage: 5V_M +3.3V +5V GND NetC153_1 NetC153_2 NetC158_1 NetC158_2 NetC159_2 NetC160_1 NetC161_1 NetC162_1 NetC162_2 NetC167_1 NetC167_2 NetC168_2 NetC169_1 NetC170_1 NetC238_1 NetL7_1 NetR108_1 NetR109_1 NetR111_1 NetR112_1 NetR116_1 NetR120_1 NetR121_1 NetR123_1 NetR124_1 NetR128_1 V_BUS_M VBUSN VBUSP
net class POWER: GND1 GND3 GND5 NetC8_2 NetC9_2 NetC10_2 NetC11_1 NetC14_2 NetC15_2 NetC16_2 NetC17_1 NetC17_2 NetC18_2 NetC19_2 NetC20_1 NetD1_2 NetD2_2 NetD3_2 NetLboost1_1 NetLboost2_1 NetLboost3_1 NetLcm1_1 NetLcm1_3 NetLcm1_5 NetLcm2_1 NetLcm2_3 NetLcm2_5 NetLdm2_1 NetLdm6_1 NetP1_1 NetP3_1 NetP5_1 NetR132_1 NetR133_1 NetR134_1 NetR135_1 NetR146_1 NetR147_1 NetR148_1 NetR149_1 NetTVS1_1 PE V_BUS_M V_N_MEAS VBUSN VBUSP
net class "Driver Signal": NetQ7_1 NetQ8_1 NetQ9_1 NetQ10_1 NetQ11_1 NetQ12_1 NetQ13_1 NetQ14_1 NetQ15_1 NetQ16_1 NetQ17_1 NetQ18_1

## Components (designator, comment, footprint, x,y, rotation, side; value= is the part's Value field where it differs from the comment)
C1 "C0805C104J5RACTU" 0805_HV 162.306,84.582 r270 top
C2 "C0805C104J5RACTU" 0805_HV 128.27,200.914 r90 bottom
C3 "C2012X5R1H475K125AB" 0805_HV 125.73,200.914 r90 bottom value=4.7uF
C4 "C0805C104J5RACTU" 0805_HV 165.354,200.914 r90 bottom
C5 "C2012X5R1H475K125AB" 0805_HV 162.814,200.914 r90 bottom value=4.7uF
C6 "C0805C104J5RACTU" 0805_HV 146.812,200.914 r90 bottom
C7 "C2012X5R1H475K125AB" 0805_HV 144.272,200.914 r90 bottom value=4.7uF
C8 "R413N310040M1M" R413N310040M1M 100.33,29.644 r90 top value=0.1uF
C9 "R413N310040M1M" R413N310040M1M 110.998,29.644 r90 top value=0.1uF
C10 "R413N310040M1M" R413N310040M1M 121.666,29.644 r90 top value=0.1uF
C11 "R413N310040M1M" R413N310040M1M 100.33,58.748 r270 top value=0.1uF
C12 "R413N310040M1M" R413N310040M1M 110.998,58.748 r270 top value=0.1uF
C13 "R413N310040M1M" R413N310040M1M 121.666,58.748 r270 top value=0.1uF
C14 "MKP1847H55035JP4" MKP1847H55035JP4 118.638,96.601 r90 top value=5uF
C15 "MKP1847H55035JP4" MKP1847H55035JP4 71.267,96.601 r90 top value=5uF
C16 "MKP1847H55035JP4" MKP1847H55035JP4 94.889,96.601 r90 top value=5uF
C17 "MKP1847H55035JP4" MKP1847H55035JP4 75.946,279.908 r270 top value=5uF
C18 "MKP1847H55035JP4" MKP1847H55035JP4 52.07,279.908 r270 top value=5uF
C19 "MKP1847H55035JP4" MKP1847H55035JP4 99.822,279.908 r270 top value=5uF
C20 "R413R34700000M" R413R34700000M 29.972,275.082 r90 top value=0.47uF
C21 "C0805C104J5RACTU" 0805_HV 186.055,156.21 r180 top
C22 "C0805C105K5RACTU" 0805_HV 186.055,153.924 r180 top
C23 "C0805C104J5RACTU" 0805_HV 189.738,183.769 r270 top
C24 "C0805C105K5RACTU" 0805_HV 185.928,186.944 r180 top
C25 "C0805C104J5RACTU" 0805_HV 173.736,151.511 r180 top
C26 "C0805C104J5RACTU" 0805_HV 173.99,184.785 r180 top
C27 "C0805C104J5RACTU" 0805_HV 189.484,134.366 r270 bottom
C28 "C2012X5R1H475K125AB" 0805_HV 191.77,134.366 r270 bottom value=4.7uF
C29 "C2012X5R1H475K125AB" 0805_HV 191.77,121.158 r90 bottom value=4.7uF
C30 "C0805C104J5RACTU" 0805_HV 189.484,121.158 r90 bottom
C31 "C0805C104J5RACTU" 0805_HV 189.23,191.262 r90 bottom
C32 "C2012X5R1H475K125AB" 0805_HV 186.944,191.262 r90 bottom value=4.7uF
C33 "C0805C101J5RACTU" 0805_HV 171.577,147.955 r90 top
C34 "C1206C106K3RACAUTO" 1206_190 180.213,106.934 r270 top value=10uF
C35 "C0805C104J5RACTU" 0805_HV 182.499,106.68 r270 top
C36 "C1206C106K3RACAUTO" 1206_190 187.579,106.934 r270 top value=10uF
C37 "C0805C104J5RACTU" 0805_HV 185.293,106.68 r270 top
C38 "C2012X5R1H475K125AB" 0805_HV 189.23,204.724 r270 bottom value=4.7uF
C39 "C0805C104J5RACTU" 0805_HV 186.944,204.724 r270 bottom
C40 "C0805C101J5RACTU" 0805_HV 171.45,181.229 r90 top
C41 "C0805C104J5RACTU" 0805_HV 191.77,130.302 r270 bottom
C42 "C2012X5R1H475K125AB" 0805_HV 189.484,130.302 r270 bottom value=4.7uF
C43 "C0805C104J5RACTU" 0805_HV 186.944,195.326 r90 bottom
C44 "C2012X5R1H475K125AB" 0805_HV 189.23,195.326 r90 bottom value=4.7uF
C45 "C0805C104J5RACTU" 0805_HV 187.452,141.097 r270 top
C46 "C0805C105K5RACTU" 0805_HV 184.912,141.097 r270 top
C47 "C0805C104J5RACTU" 0805_HV 187.452,174.371 r270 top
C48 "C0805C105K5RACTU" 0805_HV 184.912,174.371 r270 top
C49 "C0805C101J5RACTU" 0805_HV 171.577,143.637 r270 top
C50 "C0805C101J5RACTU" 0805_HV 171.45,176.911 r270 top
C51 "C1206C106K3RACAUTO" 1206_190 180.848,97.536 r270 bottom value=10uF
C52 "C1206C106K3RACAUTO" 1206_190 180.848,97.79 r270 top value=10uF
C53 "C1206C106K3RACAUTO" 1206_190 187.325,97.572 r270 top value=10uF
C54 "C1206C106K3RACAUTO" 1206_190 191.135,98.728 r270 bottom value=10uF
C55 "C0805C104J5RACTU" 0805_HV 189.611,97.572 r270 top
C56 "C0805C104J5RACTU" 0805_HV 188.595,98.044 r270 bottom
C57 "C0805C104J5RACTU" 0805_HV 268.097,156.005 r180 top
C58 "C0805C105K5RACTU" 0805_HV 268.097,153.465 r180 top
C59 "C0805C104J5RACTU" 0805_HV 270.764,134.62 r270 bottom
C60 "C2012X5R1H475K125AB" 0805_HV 273.05,134.62 r270 bottom value=4.7uF
C61 "C0805C104J5RACTU" 0805_HV 271.907,184.277 r270 top
C62 "C0805C105K5RACTU" 0805_HV 268.224,187.198 r180 top
C63 "C2012X5R1H475K125AB" 0805_HV 273.05,121.158 r90 bottom value=4.7uF
C64 "C0805C104J5RACTU" 0805_HV 270.764,121.158 r90 bottom
C65 "C0805C104J5RACTU" 0805_HV 255.729,150.749 r180 top
C66 "C0805C104J5RACTU" 0805_HV 255.905,185.293 r180 top
C67 "C0805C104J5RACTU" 0805_HV 270.764,130.302 r270 bottom
C68 "C2012X5R1H475K125AB" 0805_HV 273.05,130.302 r270 bottom value=4.7uF
C69 "C0805C104J5RACTU" 0805_HV 267.97,191.516 r90 bottom
C70 "C2012X5R1H475K125AB" 0805_HV 270.383,191.516 r90 bottom value=4.7uF
C71 "C2012X5R1H475K125AB" 0805_HV 268.097,204.978 r270 bottom value=4.7uF
C72 "C0805C104J5RACTU" 0805_HV 270.51,204.978 r270 bottom
C73 "C0805C101J5RACTU" 0805_HV 253.189,147.193 r90 top
C74 "C0805C101J5RACTU" 0805_HV 253.365,181.737 r90 top
C75 "C0805C104J5RACTU" 0805_HV 267.97,195.58 r90 bottom
C76 "C2012X5R1H475K125AB" 0805_HV 270.383,195.58 r90 bottom value=4.7uF
C77 "C0805C104J5RACTU" 0805_HV 269.445,140.335 r270 top
C78 "C0805C105K5RACTU" 0805_HV 266.905,140.335 r270 top
C79 "C0805C104J5RACTU" 0805_HV 269.367,174.879 r270 top
C80 "C0805C105K5RACTU" 0805_HV 266.827,174.879 r270 top
C81 "C0805C101J5RACTU" 0805_HV 253.189,142.875 r270 top
C82 "C0805C101J5RACTU" 0805_HV 253.365,177.546 r270 top
C83 "C0805C104J5RACTU" 0805_HV 350.012,156.21 r180 top
C84 "C0805C105K5RACTU" 0805_HV 350.012,153.67 r180 top
C85 "C0805C104J5RACTU" 0805_HV 355.092,134.112 r270 bottom
C86 "C2012X5R1H475K125AB" 0805_HV 352.806,134.112 r270 bottom value=4.7uF
C87 "C0805C104J5RACTU" 0805_HV 354.076,183.388 r270 top
C88 "C0805C105K5RACTU" 0805_HV 350.266,186.436 r180 top
C89 "C2012X5R1H475K125AB" 0805_HV 352.806,120.396 r90 bottom value=4.7uF
C90 "C0805C104J5RACTU" 0805_HV 355.092,120.396 r90 bottom
C91 "C0805C104J5RACTU" 0805_HV 338.328,150.876 r180 top
C92 "C0805C104J5RACTU" 0805_HV 338.074,184.658 r180 top
C93 "C0805C104J5RACTU" 0805_HV 352.806,129.794 r270 bottom
C94 "C2012X5R1H475K125AB" 0805_HV 355.092,129.794 r270 bottom value=4.7uF
C95 "C0805C104J5RACTU" 0805_HV 353.314,190.5 r90 bottom
C96 "C2012X5R1H475K125AB" 0805_HV 351.028,190.5 r90 bottom value=4.7uF
C97 "C2012X5R1H475K125AB" 0805_HV 350.774,204.216 r270 bottom value=4.7uF
C98 "C0805C104J5RACTU" 0805_HV 353.314,204.216 r270 bottom
C99 "C0805C101J5RACTU" 0805_HV 336.042,147.32 r90 top
C100 "C0805C101J5RACTU" 0805_HV 335.534,181.102 r90 top
C101 "C0805C104J5RACTU" 0805_HV 353.314,194.818 r90 bottom
C102 "C2012X5R1H475K125AB" 0805_HV 351.028,194.818 r90 bottom value=4.7uF
C103 "C0805C104J5RACTU" 0805_HV 351.282,140.462 r270 top
C104 "C0805C105K5RACTU" 0805_HV 348.742,140.462 r270 top
C105 "C0805C104J5RACTU" 0805_HV 351.663,174.244 r270 top
C106 "C0805C105K5RACTU" 0805_HV 349.123,174.244 r270 top
C107 "C0805C101J5RACTU" 0805_HV 336.042,143.002 r270 top
C108 "C0805C101J5RACTU" 0805_HV 335.534,176.657 r270 top
C109 "C0805C104J5RACTU" 0805_HV 131.572,176.784 r90 top
C110 "C0805C181J5GACTU" 0805_HV 132.588,170.688 r180 top
C111 "C0805C104J5RACTU" 0805_HV 143.637,176.862 r90 top
C112 "C0805C181J5GACTU" 0805_HV 156.21,170.815 r180 top
C113 "C0805C104J5RACTU" 0805_HV 155.448,176.657 r90 top
C114 "C0805C181J5GACTU" 0805_HV 144.399,170.766 r180 top
C115 "C0805C181J5GACTU" 0805_HV 102.997,89.662 r90 bottom
C116 "C0805C104J5RACTU" 0805_HV 88.646,103.886 r90 bottom
C117 "C2012X5R1H475K125AB" 0805_HV 86.614,91.44 r0 bottom value=4.7uF
C118 "C0805C104J5RACTU" 0805_HV 86.614,93.853 r0 bottom
C119 "C0805C104J5RACTU" 0805_HV 99.568,85.344 r0 bottom
C120 "C0805C181J5GACTU" 0805_HV 95.25,88.392 r180 bottom
C121 "C0805C104J5RACTU" 0805_HV 134.29,65.22 r180 top
C122 "C0805C104J5RACTU" 0805_HV 105.41,89.662 r270 bottom
C123 "C2012X5R1H475K125AB" 0805_HV 128.956,68.522 r90 top value=4.7uF
C124 "C0805C104J5RACTU" 0805_HV 131.242,68.522 r90 top
C125 "C0805C181J5GACTU" 0805_HV 86.614,88.392 r180 bottom
C126 "C0805C181J5GACTU" 0805_HV 97.536,103.886 r270 bottom
C127 "C2012X5R1H475K125AB" 0805_HV 134.29,72.078 r180 top value=4.7uF
C128 "C0805C104J5RACTU" 0805_HV 134.29,74.618 r180 top
C129 "C0805C104J5RACTU" 0805_HV 86.614,85.344 r180 bottom
C130 "C0805C181J5GACTU" 0805_HV 76.327,88.392 r180 bottom
C131 "C0805C104J5RACTU" 0805_HV 65.532,103.886 r90 bottom
C132 "C2012X5R1H475K125AB" 0805_HV 63.246,93.853 r0 bottom value=4.7uF
C133 "C0805C104J5RACTU" 0805_HV 63.246,91.44 r0 bottom
C134 "C0805C104J5RACTU" 0805_HV 76.327,85.344 r0 bottom
C135 "C0805C105K5RACTU" 0805_HV 137.414,88.138 r0 top
C136 "C0805C105K5RACTU" 0805_HV 135.128,104.14 r270 bottom
C137 "C0805C104J5RACTU" 0805_HV 137.668,104.14 r270 bottom
C138 "C0805C181J5GACTU" 0805_HV 72.009,88.392 r180 bottom
C139 "C0805C104J5RACTU" 0805_HV 82.296,89.535 r270 bottom
C140 "C0805C181J5GACTU" 0805_HV 63.246,88.392 r180 bottom
C141 "C0805C181J5GACTU" 0805_HV 74.168,103.886 r270 bottom
C142 "C0805C104J5RACTU" 0805_HV 63.246,85.344 r180 bottom
C143 "C0805C181J5GACTU" 0805_HV 122.682,88.392 r180 bottom
C144 "C0805C104J5RACTU" 0805_HV 111.887,103.886 r90 bottom
C145 "C2012X5R1H475K125AB" 0805_HV 109.601,91.44 r0 bottom value=4.7uF
C146 "C0805C104J5RACTU" 0805_HV 109.601,93.98 r0 bottom
C147 "C0805C104J5RACTU" 0805_HV 122.682,85.344 r0 bottom
C148 "C0805C181J5GACTU" 0805_HV 118.364,88.392 r180 bottom
C149 "C0805C104J5RACTU" 0805_HV 128.524,89.408 r270 bottom
C150 "C0805C181J5GACTU" 0805_HV 109.601,88.392 r180 bottom
C151 "C0805C181J5GACTU" 0805_HV 120.523,103.886 r270 bottom
C152 "C0805C104J5RACTU" 0805_HV 109.601,85.344 r180 bottom
C153 "C0805C181J5GACTU" 0805_HV 229.718,38.864 r0 top
C154 "C0805C104J5RACTU" 0805_HV 248.26,30.355 r0 top
C155 "C2012X5R1H475K125AB" 0805_HV 236.322,28.319 r90 top value=4.7uF
C156 "C0805C104J5RACTU" 0805_HV 238.862,28.319 r90 top
C157 "C0805C104J5RACTU" 0805_HV 226.416,32.768 r270 top
C158 "C0805C181J5GACTU" 0805_HV 233.02,37.086 r270 top
C159 "C0805C104J5RACTU" 0805_HV 227.178,41.3 r180 top
C160 "C0805C181J5GACTU" 0805_HV 233.782,28.323 r270 top
C161 "C0805C181J5GACTU" 0805_HV 248.26,39.499 r180 top
C162 "C0805C181J5GACTU" 0805_HV 229.692,54.712 r0 top
C163 "C0805C104J5RACTU" 0805_HV 248.234,46.33 r0 top
C164 "C2012X5R1H475K125AB" 0805_HV 236.423,44.171 r90 top value=4.7uF
C165 "C0805C104J5RACTU" 0805_HV 238.963,44.171 r90 top
C166 "C0805C104J5RACTU" 0805_HV 226.39,48.616 r270 top
C167 "C0805C181J5GACTU" 0805_HV 232.994,52.934 r270 top
C168 "C0805C104J5RACTU" 0805_HV 227.076,57.15 r180 top
C169 "C0805C181J5GACTU" 0805_HV 233.883,44.171 r270 top
C170 "C0805C181J5GACTU" 0805_HV 248.234,55.22 r180 top
C171 "C0805C105K5RACTU" 0805_HV 233.401,19.279 r270 top
C172 "C0805C105K5RACTU" 0805_HV 249.174,21.336 r180 bottom
C173 "C0805C104J5RACTU" 0805_HV 249.174,18.796 r180 bottom
C174 "CKG45KX7R2J104K290JJ" 1812 227.965,145.193 r90 bottom value=33uF
C175 "CKG45KX7R2J104K290JJ" 1812 224.155,145.161 r90 bottom value=33uF
C176 "E92X451VSN471MA50" E92X451VSN471MA50 413.258,18.208 r90 top value=470uF
C177 "EZP-E50556MTA" EZP-E50556MTA 373.888,16.002 r0 top value=55uF
C178 "CKG45KX7R2J104K290JJ" 1812 224.155,169.291 r90 bottom value=33uF
C179 "CKG45KX7R2J104K290JJ" 1812 227.965,169.291 r90 bottom value=33uF
C180 "CKG45KX7R2J104K290JJ" 1812 310.007,145.542 r90 bottom value=33uF
C181 "CKG45KX7R2J104K290JJ" 1812 306.197,145.542 r90 bottom value=33uF
C182 "CKG45KX7R2J104K290JJ" 1812 310.007,169.45 r90 bottom value=33uF
C183 "CKG45KX7R2J104K290JJ" 1812 306.197,169.45 r90 bottom value=33uF
C184 "CKG45KX7R2J104K290JJ" 1812 391.287,145.415 r90 bottom value=33uF
C185 "CKG45KX7R2J104K290JJ" 1812 387.477,145.415 r90 bottom value=33uF
C186 "E92X451VSN471MA50" E92X451VSN471MA50 291.084,18.208 r270 top value=470uF
C187 "EZP-E50556MTA" EZP-E50556MTA 330.454,16.002 r0 top value=55uF
C188 "CKG45KX7R2J104K290JJ" 1812 391.287,169.323 r90 bottom value=33uF
C189 "CKG45KX7R2J104K290JJ" 1812 387.477,169.323 r90 bottom value=33uF
C190 "C1206C106K3RACAUTO" 1206_190 105.664,175.26 r270 bottom value=10uF
C191 "C1206C106K3RACAUTO" 1206_190 107.95,175.26 r270 bottom value=10uF
C192 "C3216X5R1E336M160AC" 1206_190 99.06,175.26 r270 bottom value=33uF
C193 "C3216X5R1E336M160AC" 1206_190 96.774,175.26 r270 bottom value=33uF
C194 "C1206C106K3RACAUTO" 1206_190 94.488,175.26 r270 bottom value=10uF
C195 "C1206C106K3RACAUTO" 1206_190 92.202,175.26 r270 bottom value=10uF
C196 "C0805C104J5RACTU" 0805_HV 89.916,175.26 r270 bottom
C197 "C0805C104J5RACTU" 0805_HV 87.63,175.26 r270 bottom
C198 "C0805C104J5RACTU" 0805_HV 158.242,64.008 r270 top
C206 "C2012X5R1H475K125AB" 0805_HV 195.834,9.652 r180 bottom value=4.7uF
C207 "C2012X5R1H475K125AB" 0805_HV 195.834,14.732 r180 bottom value=4.7uF
C208 "C0805C104J5RACTU" 0805_HV 195.834,12.192 r180 bottom
C209 "C3216X5R1E336M160AC" 1206_190 195.785,32.385 r180 bottom value=33uF
C210 "C3216X5R1E336M160AC" 1206_190 195.834,29.972 r180 bottom value=33uF
C211 "C1206C106K3RACAUTO" 1206_190 203.454,41.148 r90 bottom value=10uF
C212 "C1206C106K3RACAUTO" 1206_190 201.168,41.148 r90 bottom value=10uF
C213 "C0805C104J5RACTU" 0805_HV 208.534,41.402 r90 bottom
C214 "C3216X5R1E336M160AC" 1206_190 202.184,46.482 r180 bottom value=33uF
C215 "C1206C106K3RACAUTO" 1206_190 185.2,40.132 r270 top value=10uF
C216 "C1206C106K3RACAUTO" 1206_190 180.77,44.704 r0 top value=10uF
C217 "C0805C104J5RACTU" 0805_HV 180.086,46.99 r0 top
C218 "C0805C104J5RACTU" 0805_HV 187.96,40.894 r270 top
C219 "C3216X5R1E336M160AC" 1206_190 105.41,198.374 r180 bottom value=33uF
C220 "C2012X5R1H475K125AB" 0805_HV 134.29,62.68 r180 top value=4.7uF
C221 "C1206C106K3RACAUTO" 1206_190 105.41,200.66 r180 bottom value=10uF
C222 "C0805C104J5RACTU" 0805_HV 105.41,202.946 r180 bottom
C223 "C3216X5R1E336M160AC" 1206_190 100.584,183.896 r180 bottom value=33uF
C224 "C3216X5R1E336M160AC" 1206_190 100.584,186.182 r180 bottom value=33uF
C225 "C0805C104J5RACTU" 0805_HV 100.584,188.722 r180 bottom
C226 "C3216X5R1E336M160AC" 1206_190 95.25,198.374 r180 bottom value=33uF
C227 "C2012X5R1H475K125AB" 0805_HV 137.668,93.726 r90 bottom value=4.7uF
C228 "C1206C106K3RACAUTO" 1206_190 95.25,200.66 r180 bottom value=10uF
C229 "C0805C104J5RACTU" 0805_HV 95.25,202.946 r180 bottom
C230 "EEH-ZA1H101V" SM_RADIAL_10BMM 216.408,9.144 r270 top value=100uF
C231 "C0805C104J5RACTU" 0805_HV 135.128,93.726 r90 bottom
C232 "C1206C106K3RACAUTO" 1206_190 293.624,55.88 r0 bottom value=10uF
C233 "C1206C106K3RACAUTO" 1206_190 293.624,58.166 r0 bottom value=10uF
C234 "C1206C106K3RACAUTO" 1206_190 365.506,56.134 r0 bottom value=10uF
C235 "C1206C106K3RACAUTO" 1206_190 365.506,58.674 r0 bottom value=10uF
C236 "C1206C106K3RACAUTO" 1206_190 267.97,55.88 r0 bottom value=10uF
C237 "C1206C106K3RACAUTO" 1206_190 267.97,58.166 r0 bottom value=10uF
C238 "C2012X5R1H475K125AB" 0805_HV 238.989,18.898 r0 bottom value=4.7uF
C239 "C0805C104J5RACTU" 0805_HV 238.989,21.438 r0 bottom
C240 "EEH-ZA1E101XP" SM_RADIAL_6.3BMM 220.218,21.336 r90 top value=100uF
C241 "EEH-ZA1E101XP" SM_RADIAL_6.3BMM 213.106,21.336 r90 top value=100uF
C242 "C0805C105K5RACTU" 0805_HV 150.241,68.961 r270 top
C243 "C0805C104J5RACTU" 0805_HV 131.572,188.468 r90 top
C244 "C0805C103J5RACTU" 0805_HV 138.43,176.784 r270 top
C245 "C0805C104J5RACTU" 0805_HV 136.652,184.912 r180 top
C246 "C0805C104J5RACTU" 0805_HV 155.448,188.595 r90 top
C247 "C0805C103J5RACTU" 0805_HV 162.306,176.657 r270 top
C248 "C0805C104J5RACTU" 0805_HV 160.274,185.039 r180 top
C249 "C0805C104J5RACTU" 0805_HV 143.637,188.468 r90 top
C250 "C0805C103J5RACTU" 0805_HV 150.495,176.784 r270 top
C251 "C0805C104J5RACTU" 0805_HV 148.717,184.912 r180 top
C252 "C0805C104J5RACTU" 0805_HV 126.492,170.688 r180 top
C253 "C0805C104J5RACTU" 0805_HV 126.492,176.784 r180 top
C256 "C1206C106K3RACAUTO" 1206_190 105.664,175.26 r270 top value=10uF
C257 "C0805C104J5RACTU" 0805_HV 107.95,175.26 r270 top
C258 "C3216X5R1E336M160AC" 1206_190 96.774,175.26 r270 top value=33uF
C259 "C1206C106K3RACAUTO" 1206_190 99.06,175.26 r270 top value=10uF
C260 "C0805C104J5RACTU" 0805_HV 94.488,175.26 r270 top
C261 "C0805C104J5RACTU" 0805_HV 85.598,182.372 r90 top
C262 "C1206C106K3RACAUTO" 1206_190 85.598,186.768 r270 top value=10uF
"CAUTION! High Voltage1" "DANGER HIGH VOLTAGE" IEC_HighVoltage_Small 32.004,10.668 r0 top
"CAUTION! High Voltage2" "DANGER HIGH VOLTAGE" IEC_HighVoltage_Small 411.226,290.322 r0 top
"CAUTION! High Voltage Input1" "DANGER HIGH VOLTAGE" IEC_HighVoltage_Small 147.828,146.304 r0 top
"CAUTION! High Voltage Output1" "DANGER HIGH VOLTAGE" IEC_HighVoltage_Small 345.935,52.832 r0 top
"CAUTION! HOT SURFACE!1" "CAUTION HOT SURFACE" IEC_HotSurface_Small 309.359,53.086 r0 top
"CAUTION! HOT SURFACE!!1" "CAUTION HOT SURFACE" IEC_HotSurface_Small 147.574,135.128 r0 top
D1 "MSC030SDA120B" TO-247-ress 218.175,143.18 r90 bottom
D2 "MSC030SDA120B" TO-247-ress 300.217,143.637 r90 bottom
D3 "MSC030SDA120B" TO-247-ress 382.005,143.51 r90 bottom
D4 "MSC030SDA120B" TO-247-ress 218.175,160.02 r90 bottom
D5 "MSC030SDA120B" TO-247-ress 300.217,160.147 r90 bottom
D6 "MSC030SDA120B" TO-247-ress 382.005,160.02 r90 bottom
D9 "150080VS75000" WL-SMCW_Green_0805 248.412,8.382 r90 top value="Bright Green"
D10 "150080VS75000" WL-SMCW_Green_0805 194.056,30.988 r0 top value="Bright Green"
D11 "150080VS75000" WL-SMCW_Green_0805 208.788,43.307 r90 top value="Bright Green"
D12 "150080VS75000" WL-SMCW_Green_0805 184.15,50.292 r180 top value="Bright Green"
D13 "150080VS75000" WL-SMCW_Green_0805 98.552,205.486 r0 top value="Bright Green"
FID1 "Fiducial" Fiducial10-20 443.484,88.392 r90 top
FID2 "Fiducial" Fiducial10-20 443.23,240.792 r90 top
FID3 "Fiducial" Fiducial10-20 16.51,299.212 r90 top
FID4 "Fiducial" Fiducial10-20 16.51,299.212 r90 bottom
FID5 "Fiducial" Fiducial10-20 443.23,240.792 r90 bottom
FID6 "Fiducial" Fiducial10-20 443.484,88.392 r90 bottom
Hole1 "Dia 4.3mm" "Hole-Dia 4.3mm" 201.337,76.018 r0 top locked
Hole2 "Dia 4.3mm" "Hole-Dia 4.3mm" 266.572,76.018 r0 top locked
Hole3 "Dia 4.3mm" "Hole-Dia 4.3mm" 283.337,76.018 r0 top locked
Hole4 "Dia 4.3mm" "Hole-Dia 4.3mm" 348.575,76.018 r0 top locked
Hole5 "Dia 4.3mm" "Hole-Dia 4.3mm" 365.337,76.018 r0 top locked
Hole6 "Dia 4.3mm" "Hole-Dia 4.3mm" 430.575,76.018 r0 top locked
Hole7 "Dia 4.3mm" "Hole-Dia 4.3mm" 201.337,219.815 r0 top locked
Hole8 "Dia 4.3mm" "Hole-Dia 4.3mm" 266.575,219.815 r0 top locked
Hole9 "Dia 4.3mm" "Hole-Dia 4.3mm" 283.337,219.815 r0 top locked
Hole10 "Dia 4.3mm" "Hole-Dia 4.3mm" 348.572,219.815 r0 top locked
Hole11 "Dia 4.3mm" "Hole-Dia 4.3mm" 365.335,219.815 r0 top locked
Hole12 "Dia 4.3mm" "Hole-Dia 4.3mm" 430.575,219.815 r0 top locked
J1 "HTSW-102-07-G-S" Samtec_HTSW-102-07-G-S 155.448,127.508 r180 top
J4 "HTSW-102-07-G-S" Samtec_HTSW-102-07-G-S 170.942,86.106 r270 top
J5 "CON EDGE-CARD PCB SAM MECF-30-01-L-DV-WT" HDR_F_1.27_2X30_V_SMD_MECF-30-01-L-DV-WT 155.575,100.208 r270 top value="dsPIC33CH CON60"
J6 "PJ-037AH" PJ-037AH 242.062,10.668 r0 top
J7 "Fan Connector" "Fan Connector" 265.43,53.848 r0 top
J8 "Fan Connector" "Fan Connector" 363.22,53.848 r0 top
J9 "Fan Connector" "Fan Connector" 291.084,53.848 r0 top
J12 "Fan Connector" "Fan Connector" 170.942,68.834 r270 top
L1 "MPZ2012S300AT000" 0805_HV 183.769,109.982 r0 top value="30 ohm"
L2 "MPZ2012S300AT000" 0805_HV 184.023,98.842 r0 top value="30 ohm"
L3 "MPZ2012S300AT000" 0805_HV 129.972,65.22 r180 top value="30 ohm"
L4 "MPZ2012S300AT000" 0805_HV 133.35,88.138 r180 top value="30 ohm"
L5 "MPZ2012S300AT000" 0805_HV 136.144,107.696 r0 bottom value="30 ohm"
L6 "MPZ2012S300AT000" 0805_HV 233.401,23.343 r90 top value="30 ohm"
L7 "MPZ2012S300AT000" 0805_HV 252.73,20.574 r270 bottom value="30 ohm"
L8 "MPZ2012S300AT000" 0805_HV 102.362,176.53 r180 bottom value="30 ohm"
L9 "MPZ2012S300AT000" 0805_HV 208.788,38.227 r90 top value="30 ohm"
L10 "MPZ2012S300AT000" 0805_HV 102.362,176.53 r180 top value="30 ohm"
Lboost1 "Boost_Inductor" Boost_Inductor 233.959,261.493 r0 top
Lboost2 "Boost_Inductor" Boost_Inductor 315.951,261.518 r0 top
Lboost3 "Boost_Inductor" Boost_Inductor 397.967,261.518 r0 top
Lcm1 "T60405-S6123-X140" T60405-S6123-X140 32.605,100.824 r270 top
Lcm2 "T60405-S6123-X240" T60405-S6123-X240 149.86,264.414 r56.25 top
Ldm1 "AGP4233-332ME" AGP4233-332ME 96.118,150.626 r90 top
Ldm2 "AGP4233-332ME" AGP4233-332ME 94.742,235.738 r90 top
Ldm3 "AGP4233-332ME" AGP4233-332ME 19.558,150.648 r90 top
Ldm4 "AGP4233-332ME" AGP4233-332ME 19.05,235.712 r90 top
Ldm5 "AGP4233-332ME" AGP4233-332ME 57.764,150.524 r90 top
Ldm6 "AGP4233-332ME" AGP4233-332ME 56.896,235.712 r90 top
P1 "Bush_7460408" Bush7460408 15.748,11.684 r0 top
P2 "Bush_7460408" Bush7460408 435.102,11.43 r0 top
P3 "Bush_7460408" Bush7460408 41.91,11.684 r0 top
P4 "Bush_7460408" Bush7460408 435.102,33.274 r0 top
P5 "Bush_7460408" Bush7460408 68.58,11.684 r0 top
P6 "Bush_7460408" Bush7460408 434.848,54.864 r0 top
P7 "Bush_7460408" Bush7460408 101.854,11.684 r0 top
P8 "Quick Connect" "Quick Connect-4.75mm" 220.726,235.204 r0 top (schematic designator p8)
P9 "Quick Connect" "Quick Connect-4.75mm" 302.768,235.204 r180 top (schematic designator p9)
P10 "Quick Connect" "Quick Connect-4.75mm" 384.81,235.204 r180 top (schematic designator p10)
Q1 "2N7002" SOT-23 169.799,139.827 r180 top value=60V
Q2 "2N7002" SOT-23 169.926,173.101 r180 top value=60V
Q3 "2N7002" SOT-23 251.665,138.811 r180 top value=60V
Q4 "2N7002" SOT-23 251.968,173.482 r180 top value=60V
Q5 "2N7002" SOT-23 334.264,139.192 r180 top value=60V
Q6 "2N7002" SOT-23 334.01,172.974 r180 top value=60V
Q7 "MSC040SMA120B" TO-247 206.375,187.554 r270 top
Q8 "MSC040SMA120B" TO-247 206.375,153.772 r270 top
Q9 "MSC040SMA120B" TO-247 206.375,170.688 r270 top
Q10 "MSC040SMA120B" TO-247 206.375,136.855 r270 top
Q11 "MSC040SMA120B" TO-247 288.417,187.655 r270 top
Q12 "MSC040SMA120B" TO-247 288.417,153.924 r270 top
Q13 "MSC040SMA120B" TO-247 288.417,170.815 r270 top
Q14 "MSC040SMA120B" TO-247 288.417,137.033 r270 top
Q15 "MSC040SMA120B" TO-247 370.332,187.681 r270 top
Q16 "MSC040SMA120B" TO-247 370.332,153.899 r270 top
Q17 "MSC040SMA120B" TO-247 370.332,170.815 r270 top
Q18 "MSC040SMA120B" TO-247 370.332,137.033 r270 top
R2 "CRCW080510K0FKEA" 0805_HV 162.306,88.646 r90 top value=4.7k
R3 "CRCW080510K0FKEA" 0805_HV 166.116,87.63 r180 top value=68.1
R4 "AX10GKE" AX10GKE 11.43,268.986 r180 top
R5 "CRCW08050000Z0EA" 0805_HV 187.452,150.749 r90 top value=0
R6 "CRCW08050000Z0EA" 0805_HV 187.198,183.769 r90 top value=0
R7 "CRCW0805100RFKEAC" 0805_HV 169.037,147.955 r270 top value=348
R8 "CRCW08050000Z0EA" 0805_HV 184.912,150.749 r270 top value=0
R9 "CRCW0805100RFKEAC" 0805_HV 168.91,181.229 r270 top value=348
R10 "CRCW08050000Z0EA" 0805_HV 184.658,183.769 r270 top value=0
R11 "CRCW12064R70FKEAHP" 1206_190 188.468,147.066 r0 top value=2.2
R12 "CRCW12064R70FKEAHP" 1206_190 188.468,180.34 r0 top value=2.2
R13 "CRCW12062R20FKEAHP" 1206_190 188.468,144.78 r0 top value=4.7
R14 "CRCW0805100RFKEAC" 0805_HV 169.418,151.511 r180 top value=348
R15 "CRCW12062R20FKEAHP" 1206_190 188.468,178.054 r0 top value=4.7
R16 "CRCW0805100RFKEAC" 0805_HV 169.672,184.785 r180 top value=348
R17 "CRCW0805680RFKEA" 0805_HV 169.037,143.637 r270 top value=680
R18 "CRCW0805680RFKEA" 0805_HV 168.91,176.911 r270 top value=680
R19 "CRCW0805100RFKEAC" 0805_HV 169.799,136.779 r0 top value=348
R20 "CRCW0805100RFKEAC" 0805_HV 169.926,170.053 r0 top value=348
R21 "CRCW08050000Z0EA" 0805_HV 184.023,96.302 r0 top value=0
R22 "CRCW08050000Z0EA" 0805_HV 269.445,149.987 r90 top value=0
R23 "CRCW08050000Z0EA" 0805_HV 269.367,184.277 r90 top value=0
R24 "CRCW0805100RFKEAC" 0805_HV 250.649,147.193 r270 top value=348
R25 "CRCW08050000Z0EA" 0805_HV 266.905,149.987 r270 top value=0
R26 "CRCW0805100RFKEAC" 0805_HV 250.825,181.737 r270 top value=348
R27 "CRCW08050000Z0EA" 0805_HV 266.827,184.277 r270 top value=0
R28 "CRCW12064R70FKEAHP" 1206_190 270.461,146.304 r0 top value=2.2
R29 "CRCW12064R70FKEAHP" 1206_190 270.637,180.848 r0 top value=2.2
R30 "CRCW12062R20FKEAHP" 1206_190 270.461,144.018 r0 top value=4.7
R31 "CRCW0805100RFKEAC" 0805_HV 251.411,150.749 r180 top value=348
R32 "CRCW12062R20FKEAHP" 1206_190 270.637,178.562 r0 top value=4.7
R33 "CRCW0805100RFKEAC" 0805_HV 251.587,185.293 r180 top value=348
R34 "CRCW0805680RFKEA" 0805_HV 250.649,142.875 r270 top value=680
R35 "CRCW0805680RFKEA" 0805_HV 250.825,177.546 r270 top value=680
R36 "CRCW0805100RFKEAC" 0805_HV 251.665,135.763 r0 top value=348
R37 "CRCW0805100RFKEAC" 0805_HV 251.968,170.434 r0 top value=348
R38 "CRCW08050000Z0EA" 0805_HV 351.282,150.114 r90 top value=0
R39 "CRCW08050000Z0EA" 0805_HV 351.536,183.388 r90 top value=0
R40 "CRCW0805100RFKEAC" 0805_HV 332.994,147.32 r270 top value=348
R41 "CRCW08050000Z0EA" 0805_HV 348.742,150.114 r270 top value=0
R42 "CRCW0805100RFKEAC" 0805_HV 332.994,181.102 r270 top value=348
R43 "CRCW08050000Z0EA" 0805_HV 348.996,183.388 r270 top value=0
R44 "CRCW12064R70FKEAHP" 1206_190 352.298,146.431 r0 top value=2.2
R45 "CRCW12064R70FKEAHP" 1206_190 352.806,180.086 r0 top value=2.2
R46 "CRCW12062R20FKEAHP" 1206_190 352.298,144.018 r0 top value=4.7
R47 "CRCW0805100RFKEAC" 0805_HV 334.01,150.876 r180 top value=348
R48 "CRCW12062R20FKEAHP" 1206_190 352.806,177.8 r0 top value=4.7
R49 "CRCW0805100RFKEAC" 0805_HV 333.756,184.658 r180 top value=348
R50 "CRCW0805680RFKEA" 0805_HV 332.994,143.002 r270 top value=680
R51 "CRCW0805680RFKEA" 0805_HV 332.994,176.657 r270 top value=680
R52 "CRCW0805100RFKEAC" 0805_HV 333.502,136.144 r0 top value=348
R53 "CRCW0805100RFKEAC" 0805_HV 334.01,169.926 r0 top value=348
R54 "TNPW08052K20BEEA" 0805_HV 136.652,181.102 r270 top value=2.2k
R55 "CRCW0805120RFKTA" 0805_HV 160.909,68.961 r90 top value=120
R56 "CRCW080568R1FKEA" 0805_HV 136.652,170.688 r180 top value=348
R57 "TNPW080540K2BEEA" 0805_HV 131.572,181.102 r90 top value=40.2k
R58 "TNPW08051K00BEEA" 0805_HV 136.652,173.228 r0 top value=1k
R59 "TNPW080510K0BEEA" 0805_HV 132.588,173.228 r0 top value=10k
R60 "TNPW08052K20BEEA" 0805_HV 160.528,181.229 r270 top value=2.2k
R61 "TNPW08052K20BEEA" 0805_HV 132.334,184.912 r180 top value=2.2k
R62 "CRCW080568R1FKEA" 0805_HV 160.274,170.815 r180 top value=348
R63 "TNPW080540K2BEEA" 0805_HV 155.448,181.229 r90 top value=40.2k
R64 "TNPW08051K00BEEA" 0805_HV 160.274,173.355 r0 top value=1k
R65 "TNPW080510K0BEEA" 0805_HV 156.21,173.355 r0 top value=10k
R66 "TNPW08052K20BEEA" 0805_HV 148.717,181.18 r270 top value=2.2k
R67 "TNPW0805160RBEEA" 0805_HV 134.112,181.102 r270 top value=160R
R68 "CRCW080568R1FKEA" 0805_HV 148.463,170.766 r180 top value=348
R69 "TNPW080540K2BEEA" 0805_HV 143.637,181.131 r90 top value=40.2k
R70 "TNPW080510K0BEEA" 0805_HV 148.463,173.306 r0 top value=1k
R71 "TNPW080510K0BEEA" 0805_HV 144.399,173.306 r0 top value=10k
R72 "TNPW12061M00BXTY" 1206_190 86.946,109.601 r180 bottom value=1M
R73 "TNPW12061M00BXTY" 1206_190 92.026,109.601 r180 bottom value=1M
R74 "CRCW08057K50FKEA" 0805_HV 99.568,88.392 r0 bottom value=348
R75 "TNPW12061M00BXTY" 1206_190 97.155,109.601 r180 bottom value=1M
R76 "CRCW08054K70FKEA" 0805_HV 95.25,91.44 r0 bottom value=4.7k
R77 "CRCW08054K70FKEA" 0805_HV 99.568,91.44 r0 bottom value=4.7k
R78 "TNPW12062K00BEEA" 1206_190 102.235,109.601 r180 bottom value=2k
R79 "CRCW080568R1FKEA" 0805_HV 103.886,85.344 r0 bottom value=348
R80 "CRCW08054K70FKEA" 0805_HV 90.932,91.44 r180 bottom value=4.7k
R81 "CRCW08054K70FKEA" 0805_HV 90.932,88.392 r180 bottom value=4.7k
R82 "TNPW12062K00BEEA" 1206_190 100.076,103.378 r270 bottom value=2k
R83 "CRCW08057K50FKEA" 0805_HV 90.932,85.344 r0 bottom value=348
R84 "TNPW12061M00BXTY" 1206_190 63.578,109.601 r180 bottom value=1M
R85 "TNPW12061M00BXTY" 1206_190 68.658,109.601 r180 bottom value=1M
R86 "CRCW08057K50FKEA" 0805_HV 79.756,89.535 r270 bottom value=348
R87 "TNPW12061M00BXTY" 1206_190 73.787,109.601 r180 bottom value=1M
R88 "CRCW08054K70FKEA" 0805_HV 72.009,91.44 r0 bottom value=4.7k
R89 "CRCW08054K70FKEA" 0805_HV 76.327,91.44 r0 bottom value=4.7k
R90 "TNPW12062K00BEEA" 1206_190 78.867,109.601 r180 bottom value=2k
R91 "CRCW080568R1FKEA" 0805_HV 80.645,85.344 r0 bottom value=348
R92 "CRCW08054K70FKEA" 0805_HV 67.691,91.44 r180 bottom value=4.7k
R93 "CRCW08054K70FKEA" 0805_HV 67.691,88.392 r180 bottom value=4.7k
R94 "TNPW12062K00BEEA" 1206_190 76.708,103.378 r270 bottom value=2k
R95 "CRCW08057K50FKEA" 0805_HV 67.691,85.344 r0 bottom value=348
R96 "TNPW12061M00BXTY" 1206_190 110.109,109.601 r180 bottom value=1M
R97 "TNPW12061M00BXTY" 1206_190 115.189,109.601 r180 bottom value=1M
R98 "CRCW08057K50FKEA" 0805_HV 126.111,89.408 r270 bottom value=348
R99 "TNPW12061M00BXTY" 1206_190 120.269,109.601 r180 bottom value=1M
R100 "CRCW08054K70FKEA" 0805_HV 118.364,91.44 r0 bottom value=4.7k
R101 "CRCW08054K70FKEA" 0805_HV 122.682,91.44 r0 bottom value=4.7k
R102 "TNPW12062K00BEEA" 1206_190 125.349,109.601 r180 bottom value=2k
R103 "CRCW080568R1FKEA" 0805_HV 127,85.344 r0 bottom value=348
R104 "CRCW08054K70FKEA" 0805_HV 114.046,91.44 r180 bottom value=4.7k
R105 "CRCW08054K70FKEA" 0805_HV 114.046,88.392 r180 bottom value=4.7k
R106 "TNPW12062K00BEEA" 1206_190 123.063,103.378 r270 bottom value=2k
R107 "CRCW08057K50FKEA" 0805_HV 114.046,85.344 r0 bottom value=348
R108 "TNPW12061M00BXTY" 1206_190 268.755,37.846 r0 top value=1M
R109 "TNPW12061M00BXTY" 1206_190 263.851,37.846 r0 top value=1M
R110 "CRCW08057K50FKEA" 0805_HV 229.718,36.324 r180 top value=348
R111 "TNPW12061M00BXTY" 1206_190 259.181,37.846 r0 top value=1M
R112 "CRCW08054K70FKEA" 0805_HV 235.814,37.086 r90 top value=4.7k
R113 "CRCW08054K70FKEA" 0805_HV 233.782,40.538 r180 top value=4.7k
R114 "TNPW12062K74BEEN" 1206_190 254.023,37.846 r0 top value=2.74k
R115 "CRCW080568R1FKEA" 0805_HV 226.416,37.086 r90 top value=348
R116 "CRCW08054K70FKEA" 0805_HV 235.814,32.768 r270 top value=4.7k
R117 "CRCW08054K70FKEA" 0805_HV 233.02,32.768 r270 top value=4.7k
R118 "TNPW12062K74BEEN" 1206_190 248.768,41.808 r180 top value=2.74k
R119 "CRCW08057K50FKEA" 0805_HV 231.242,28.346 r90 top value=348
R120 "TNPW12061M00BXTY" 1206_190 268.755,48.006 r0 top value=1M
R121 "TNPW12061M00BXTY" 1206_190 263.929,48.006 r0 top value=1M
R122 "CRCW08057K50FKEA" 0805_HV 229.692,52.172 r180 top value=348
R123 "TNPW12061M00BXTY" 1206_190 259.103,48.006 r0 top value=1M
R124 "CRCW08054K70FKEA" 0805_HV 235.712,55.245 r270 top value=4.7k
R125 "CRCW08054K70FKEA" 0805_HV 232.994,57.252 r90 top value=4.7k
R126 "TNPW12062K74BEEN" 1206_190 254.023,48.006 r0 top value=2.74k
R127 "CRCW080568R1FKEA" 0805_HV 226.39,52.934 r90 top value=348
R128 "CRCW08054K70FKEA" 0805_HV 235.788,48.616 r270 top value=4.7k
R129 "CRCW08054K70FKEA" 0805_HV 232.994,48.616 r270 top value=4.7k
R130 "TNPW12062K74BEEN" 1206_190 248.918,57.76 r180 top value=2.74k
R131 "CRCW08057K50FKEA" 0805_HV 231.343,44.171 r90 top value=348
R132 "CRCW2010510KJNEF" 2010 381.014,16.51 r0 bottom value=510k
R133 "CRCW2010510KJNEF" 2010 406.146,10.922 r270 bottom value=510k
R134 "CRCW2010510KJNEF" 2010 373.62,16.51 r0 bottom value=510k
R135 "CRCW2010510KJNEF" 2010 406.146,18.274 r270 bottom value=510k
R136 "CRCW2010510KJNEF" 2010 366.268,16.51 r0 bottom value=510k
R137 "CRCW2010510KJNEF" 2010 406.146,25.668 r270 bottom value=510k
R138 "CRCW12062R20FKEAHP" 1206_190 193.548,180.34 r0 top value=4.7
R139 "CRCW12062R20FKEAHP" 1206_190 193.548,147.066 r180 top value=4.7
R140 "CRCW12062R20FKEAHP" 1206_190 193.548,178.054 r0 top value=4.7
R141 "CRCW12062R20FKEAHP" 1206_190 193.548,144.78 r180 top value=4.7
R142 "CRCW12062R20FKEAHP" 1206_190 275.717,180.848 r0 top value=4.7
R143 "CRCW12062R20FKEAHP" 1206_190 275.717,146.304 r180 top value=4.7
R144 "CRCW12062R20FKEAHP" 1206_190 275.717,178.562 r0 top value=4.7
R145 "CRCW12062R20FKEAHP" 1206_190 275.717,144.018 r180 top value=4.7
R146 "CRCW2010510KJNEF" 2010 338.074,16.51 r0 bottom value=510k
R147 "CRCW2010510KJNEF" 2010 298.45,25.4 r90 bottom value=510k
R148 "CRCW2010510KJNEF" 2010 330.708,16.51 r0 bottom value=510k
R149 "CRCW2010510KJNEF" 2010 298.45,18.034 r90 bottom value=510k
R150 "CRCW12062R20FKEAHP" 1206_190 357.632,180.086 r0 top value=4.7
R151 "CRCW12062R20FKEAHP" 1206_190 357.505,146.431 r180 top value=4.7
R152 "CRCW2010510KJNEF" 2010 323.342,16.51 r0 bottom value=510k
R153 "CRCW2010510KJNEF" 2010 298.45,10.668 r90 bottom value=510k
R154 "CRCW12062R20FKEAHP" 1206_190 357.632,177.8 r0 top value=4.7
R155 "CRCW12062R20FKEAHP" 1206_190 357.505,144.018 r180 top value=4.7
R162 "CRCW08050000Z0EA" 0805_HV 102.362,173.99 r180 bottom value=0
R163 "CRCW08054K70FKEA" 0805_HV 248.412,12.446 r90 top value=348
R164 "CRCW08054K70FKEA" 0805_HV 198.12,30.988 r0 top value=348
R165 "CRCW08052K00FKEAC" 0805_HV 208.788,47.625 r90 top value=348
R166 "CRCW08051K00FKEA" 0805_HV 180.086,50.292 r180 top value=1k
R167 "CRCW0805348RFKEA" 0805_HV 197.612,47.752 r180 bottom value=348
R168 "CRCW08050000Z0EA" 0805_HV 189.484,6.35 r0 bottom value=0
R169 "CRCW08055K00FKTA" 0805_HV 102.616,205.486 r0 top value=5k
R170 "CRCW08050000Z0EA" 0805_HV 93.98,180.848 r0 bottom value=0
R171 "TNPW120649R9BEEA" 1206_190 133.35,191.77 r0 top value=49.9
R172 "TNPW08052K20BEEA" 0805_HV 156.21,185.039 r180 top value=2.2k
R173 "TNPW0805160RBEEA" 0805_HV 157.988,181.229 r270 top value=160R
R174 "TNPW120649R9BEEA" 1206_190 157.48,192.024 r0 top value=49.9
R175 "TNPW08052K20BEEA" 0805_HV 144.399,184.912 r180 top value=2.2k
R176 "TNPW0805160RBEEA" 0805_HV 146.177,181.18 r270 top value=160R
R177 "TNPW120649R9BEEA" 1206_190 145.415,191.77 r0 top value=49.9
R178 "CRCW080510K0FKEA" 0805_HV 158.242,74.168 r90 top value=10k
R180 "CRCW08054R99FKEAC" 0805_HV 78.486,192.278 r90 top value=4.99
R181 "CRCW08054R99FKEAC" 0805_HV 80.772,192.278 r90 top value=4.99
R182 "CRCW08054R99FKEAC" 0805_HV 83.058,192.278 r90 top value=4.99
R183 "CRCW08054R99FKEAC" 0805_HV 85.344,192.278 r90 top value=4.99
Rsurge1 "AW220KE" AW220KE 28.067,181.864 r180 top
Rsurge2 "AW220KE" AW220KE 28.08,201.676 r180 top
S1 "M2011SS1W01" M2011SS1W01 229.87,8.636 r90 top
SW1 "EW60-1A3-BL12D04,00000" EW60-1A3-BL12D04,00000 41.91,178.182 r0 top
SW2 "EW60-1A3-BL12D04,00000" EW60-1A3-BL12D04,00000 41.9,197.866 r0 top
TP_BUSM "5012" Keystone5012 254.508,42.926 r0 top
TP_DGND1 "5011" Keystone5011 183.007,91.44 r90 top
TP_EN1 "5127" Keystone5127 168.91,132.588 r90 top value=Blue
TP_G1 "5010" Keystone5010 174.244,189.738 r90 top
TP_G2 "5012" Keystone5012 173.736,155.956 r90 top
TP_G3 "5010" Keystone5010 256.032,190.246 r90 top
TP_G4 "5012" Keystone5012 256.032,155.702 r90 top
TP_G5 "5010" Keystone5010 337.82,190.246 r90 top
TP_G6 "5012" Keystone5012 337.312,155.702 r90 top
TP_GND "5012" Keystone5012 138.176,78.232 r90 top
TP_GND1 "5011" Keystone5011 197.104,159.258 r90 top
TP_GND2 "5011" Keystone5011 278.892,159.766 r90 top
TP_GND3 "5011" Keystone5011 360.68,159.766 r90 top
TP_GS1 "5010" Keystone5010 193.802,175.006 r90 top
TP_GS2 "5012" Keystone5012 193.802,141.732 r90 top
TP_GS3 "5010" Keystone5010 276.098,175.514 r90 top
TP_GS4 "5012" Keystone5012 276.098,140.97 r90 top
TP_GS5 "5010" Keystone5010 358.14,174.752 r90 top
TP_GS6 "5012" Keystone5012 357.886,140.97 r90 top
TP_IIn1 "5011" Keystone5011 139.192,190.5 r0 top
TP_IIn2 "5010" Keystone5010 163.322,190.754 r90 top
TP_IIn3 "5127" Keystone5127 151.257,190.5 r90 top value=Blue
TP_IL1 "5011" Keystone5011 134.62,167.64 r0 top
TP_IL2 "5010" Keystone5010 158.242,167.767 r90 top
TP_IL3 "5127" Keystone5127 146.431,167.64 r90 top value=Blue
TP_N1 "5012" Keystone5012 429.26,33.218 r0 top
TP_PE1 "5012" Keystone5012 97.79,3.81 r90 top
TP_V1 "5011" Keystone5011 27.432,4.064 r90 top
TP_V2 "5010" Keystone5010 53.848,4.064 r90 top
TP_V3 "5127" Keystone5127 80.264,4.064 r90 top value=Blue
TP_VBUSMN_Fdbk1 "5011" Keystone5011 223.012,57.404 r0 top
TP_VBUSPM_Fdbk1 "5010" Keystone5010 223.266,40.64 r0 top
TP_VL1 "5011" Keystone5011 133.096,78.232 r180 top
TP_VL2 "5010" Keystone5010 138.176,84.328 r180 top
TP_VL3 "5127" Keystone5127 133.35,84.328 r180 top value=Blue
TP_VL7 "5010" Keystone5010 429.006,3.81 r0 top
TP_VL8 "5011" Keystone5011 428.752,47.244 r0 top
TP_VLI1 "5011" Keystone5011 101.854,119.888 r90 top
